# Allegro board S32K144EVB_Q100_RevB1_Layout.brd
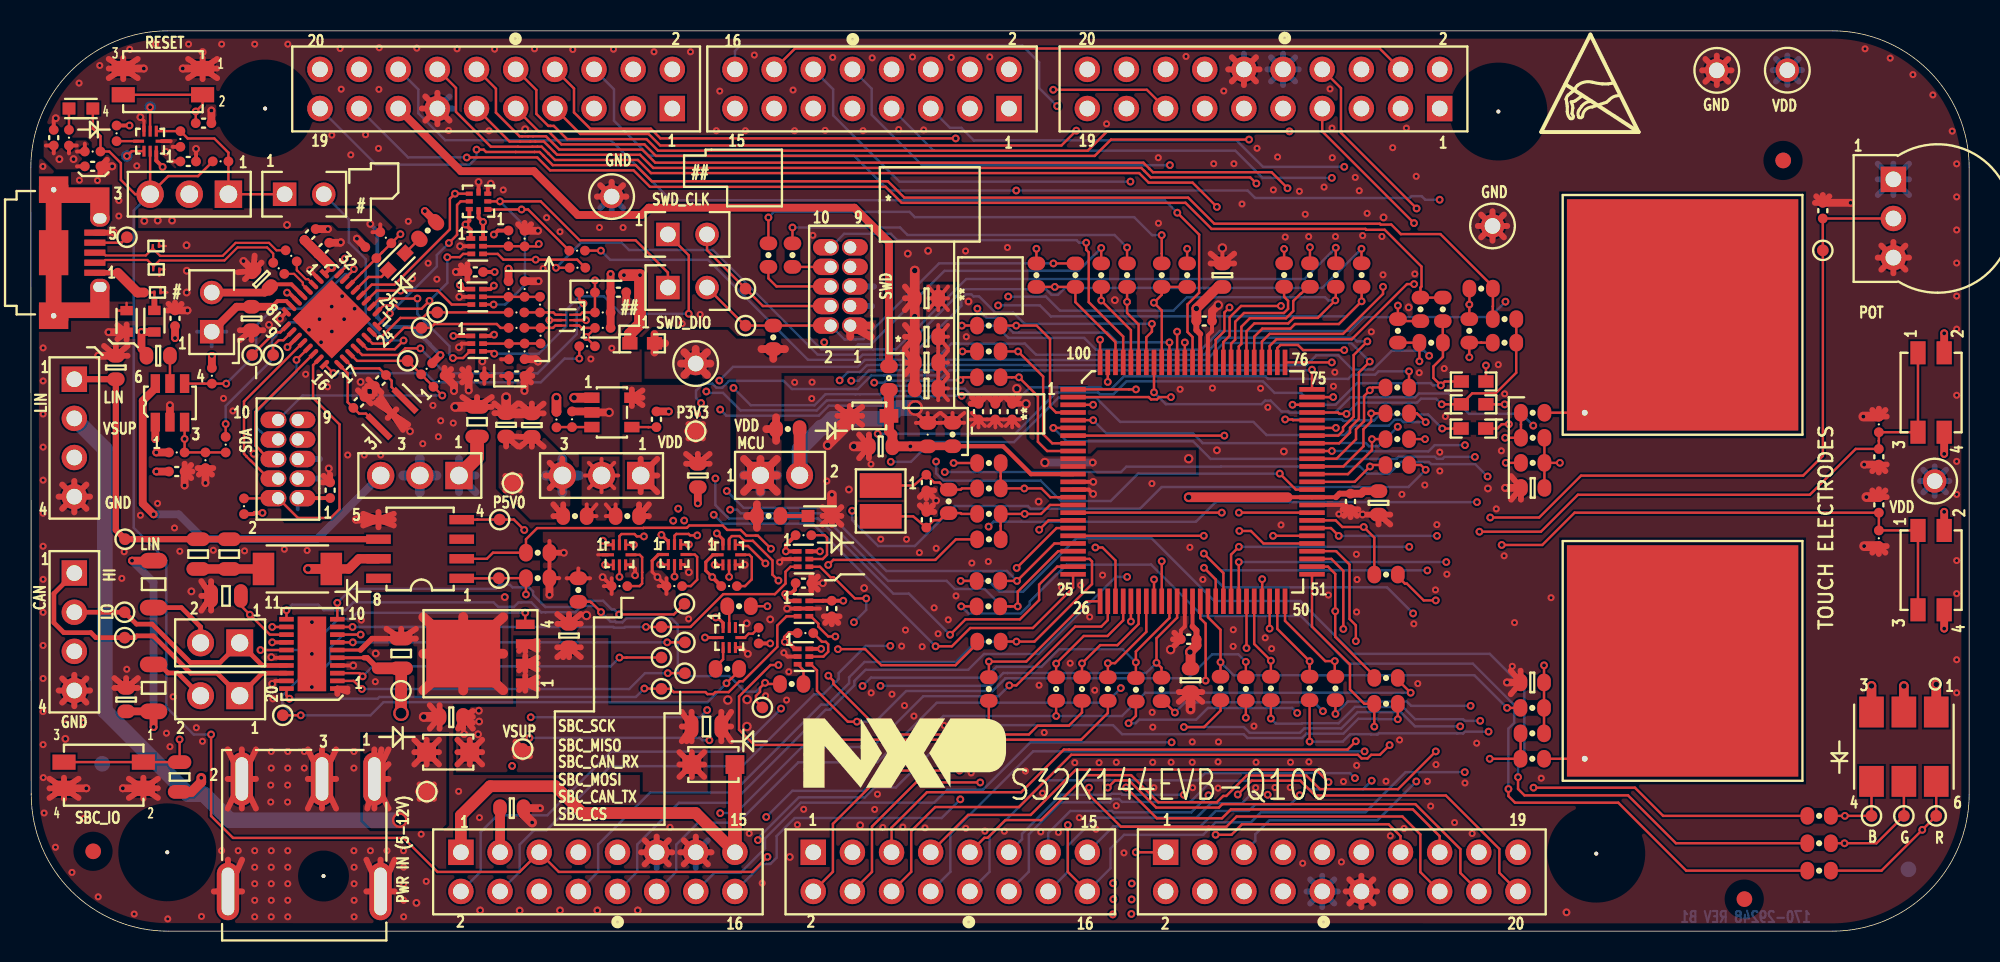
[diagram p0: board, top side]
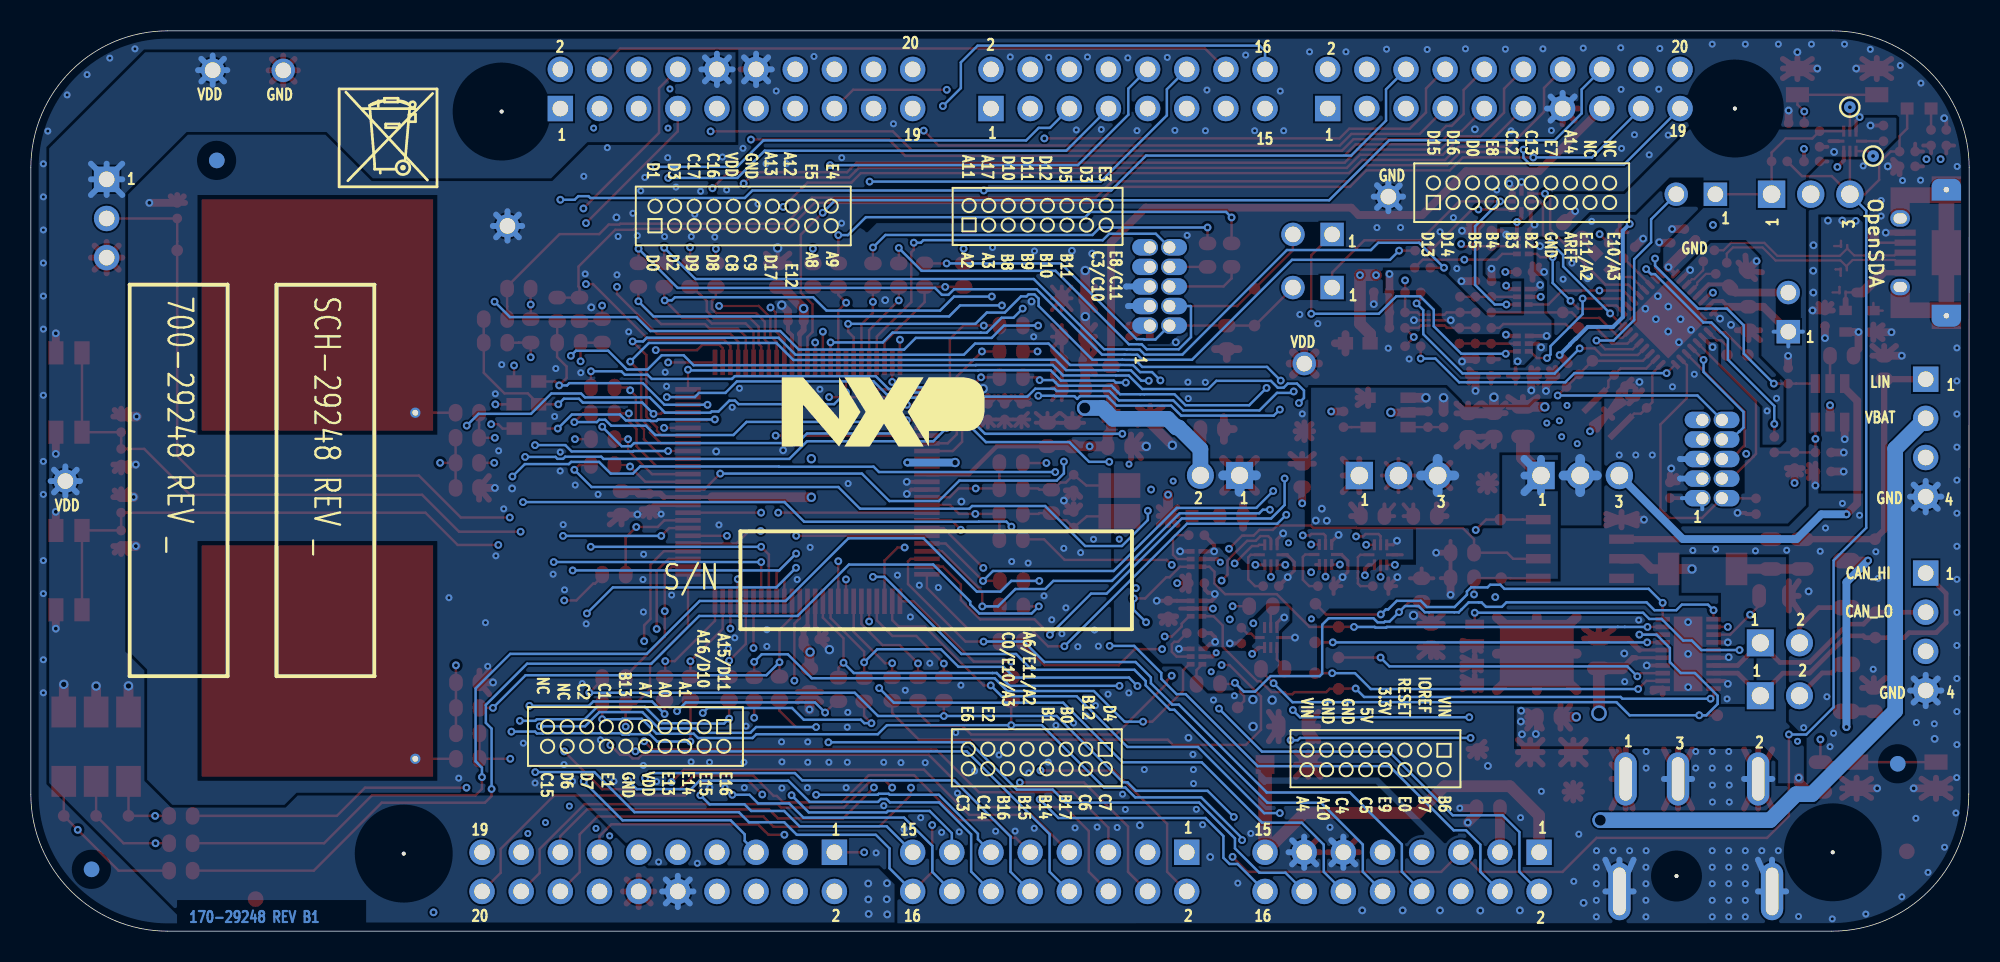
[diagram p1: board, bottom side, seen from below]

Outline 125.76 x 58.42 mm; copper layers: TOP, L2_GND, L3_MIX, BOTTOM. Coordinates in mm from the lower left corner of the outline.
Outline path: 0,49.53 0.03,8.89 0.03,8.89 arc(2.63,2.6) 8.92,0 116.87,0 arc(123.15,2.6) 125.76,8.89 125.76,49.53 arc(123.15,55.82) 116.87,58.42 8.89,58.42 arc(2.6,55.82) 0,49.53

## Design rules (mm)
net group CLOCK: nets SDA_EXTAL SDA_XTAL
net group SDA_USB_CONN_D: nets SDA_USB_CONN_DN SDA_USB_CONN_DP
net group USB_SI_CONN_D: nets SDA_USB_DN SDA_USB_DP
net group POW: nets MIC2005_CSLEW P5V_SDA POWER_EN SDA_RST SDA_USB_P5V_SENSE VREFH VTRG_EN
net group POWER_SPACE: nets P5V0_SDA_USB_CONN_VBUS P5V_SDA_PSW PWR_LED SDA_VOUT33 VIN
nets with their own width: min track width 0.254; nets GND

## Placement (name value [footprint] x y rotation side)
C1  1000pF  [CC0402_25]  11.21 52.43 0 top
C2  4.7uF  [CC0402_25]  1.49 51.49 90 top
C3  4.7uF  [CC0402_25]  10.21 49.94 0 top
C4  0.1UF  [CC0402_25]  4.01 49.63 0 top
C5  0.1UF  [CC0402_25]  116.26 46.75 90 top
C6  1.0UF  [CC0402_25]  18.12 45.2 45 top
C7  0.1UF  [CC0402_25]  19 44.31 45 top
C8  4.7uF  [CC0402_25]  28.83 42.77 180 top
C9  2.2UF  [CC0603_OV]  14.97 42.31 135 top
C10  0.1UF  [CC0402_25]  38.12 41.46 0 top
C11  10uF  [CC0402_25]  9.35 39.77 90 top
C12  10uF  [CC0603_OV]  14.32 39.75 270 top
C15  18PF  [CC0603_OV]  8.26 37.34 0 top
C16  0.1UF  [CC0402_25]  119.89 30.78 270 top
C17  220PF  [CC0603_OV]  5.51 36.58 90 top
C18  4.7uF  [CC0402_25]  28.92 36.03 180 top
C19  0.1UF  [CC0402_25]  31.52 36.03 0 top
C20  22PF  [CC0402_25]  22.68 35.73 225 top
C21  10uF  [CC0603_OV]  30.84 32.85 90 top
C22  0.1uF  [CC0603_OV]  32.5 32.84 90 top
C23  22PF  [CC0402_25]  21.29 34.31 45 top
C24  10uF  [CC0603_OV]  43.27 29.57 270 top
C25  0.1UF  [CC0402_25]  9.47 29.82 0 top
C26  0.1UF  [CC0402_25]  19.42 28.61 90 top
C27  6.8uF  [CC0805_OV]  28.95 33.06 90 top
C28  0.1UF  [CC0402_25]  119.9 27.66 90 top
C29  0.01uf  [CC0603_OV]  27.28 13.9 180 top
C40  4700 PF  [CC0603_OV]  6.18 15.02 90 top
C43  1UF  [CC0603_OV]  58.11 38.57 180 top
C47  0.1uF  [CC0603_OV]  34.92 19.18 90 top
C49  2.2UF  [CC0603_OV]  31.2 7.98 0 top
C59  0.01UF  [CC0402_25]  40.59 33.21 90 top
C126  12PF  [CC0402_25]  58.1 29.11 270 top
C127  12PF  [CC0402_25]  58.1 26.69 90 top
C128  22uF  [CC0805_OV]  43.83 13.28 0 top
C129  1UF  [CC0603_OV]  58.11 35.22 180 top
C131  1UF  [CC0603_OV]  58.11 36.89 180 top
C133  1UF  [CC0603_OV]  77.3 42.56 90 top
C137  1UF  [CC0603_OV]  75.24 16.28 270 top
C140  0.1uF  [CC0402_25]  62.58 33.71 90 top
C141  0.1uF  [CC0402_25]  75.12 18.94 180 top
C142  0.1uF  [CC0402_25]  76.13 39.59 0 top
C143  0.1uF  [CC0402_25]  85.62 27.88 270 top
C144  0.1uF  [CC0402_25]  61.48 33.71 90 top
C145  0.1uF  [CC0402_25]  63.67 33.71 90 top
C146  1UF  [CC0603_OV]  87.43 27.79 270 top
C147  1000PF  [CC0603_OV]  58.11 41.06 180 top
C148  1000PF  [CC0603_OV]  55.14 31.46 180 top
C533  10pF  [CC0603_OV]  97.44 28.76 180 top
C535  10pF  [CC0603_OV]  97.41 16.14 180 top
C536  6.8uF  [CC0805_OV]  12.66 21.76 180 top
C537  0.1UF  [CC0402_25]  51.96 20.93 270 top
C538  0.1UF  [CC0402_25]  50.13 22.58 0 top
D1  RED  [LED_0603]  3.25 53.38 0 top
D2  LED GREEN  [LED_0603]  23.73 43.44 225 top
D3  GREEN  [LED_0603]  51.2 26.94 0 top
D6  PMEG3050EP  [SOD-128]  17.29 23.5 180 top
D7  BZX384-C30  [SOD323]  54.4 33.44 90 top
D9  PNS40010ER  [SOD123W]  27.08 11.62 180 top
D11  LED RED/GRN/BL  [LED6_5X6MM]  121.52 11.97 270 top
D13  PNS40010ER  [SOD123W]  44.28 10.81 0 top
D17  PESD5V0R1BSF  [DSN0603-2]  8.22 41.45 180 top
D18  PESD5V0R1BSF  [DSN0603-2]  8.12 44.46 180 top
D19  PESD5V0R1BSF  [DSN0603-2]  8.14 42.94 180 top
J1  CON 2X8  [CON2X8_2P54_TH]  63.46 53.38 270 top
J2  CON 2X10  [CON20_2P54_TH]  41.62 53.38 270 top
J3  CON 2X8  [CON2X8_2P54_TH]  27.9 5.12 90 top
J4  CON 2X8  [CON2X8_2P54_TH]  50.76 5.12 90 top
J5  CON 2X10  [CON20_2P54_TH]  73.62 5.12 90 top
J6  CON 2X10  [CON20_2P54_TH]  91.4 53.38 270 top
J7  USB_MICRO_AB  [CON_MICROAB_10F_25_SM_RA]  1.58 44.02 0 top
J8  HDR 1X2 TH  [SH_HDR102_BOTTOM]  41.33 45.21 90 top
J9  HDR 1X2 TH  [SH_HDR102_BOTTOM]  11.73 38.9 180 top
J10  HDR 1X3  [HDR103_A]  39.57 29.57 270 top
J11  HDR 1X4 RA  [CON_HDR_4M_100_TH_RA]  2.82 35.81 270 top
J12  HDR 2X5  [CON_2RH_10_50]  17.32 28.09 90 top
J13  HDR 1X4 RA  [CON_HDR_4M_100_TH_RA]  2.82 23.24 270 top
J14  HDR 2X5  [CON_2RH_10_50]  53.16 39.29 90 top
J15  HDR1X2  [HDR1X2_5P48X2P69]  47.34 29.58 0 top
J16  CON PWR 3  [CON3_PWR_JACK_TH_PJ051A]  22.29 9.88 90 top
J104  HDR 1X3  [HDR103_A]  12.82 47.82 270 top
J105  HDR 1X2 TH  [SH_HDR102_BOTTOM]  16.46 47.82 90 top
J106  HDR 1X2 TH  [SH_HDR102_BOTTOM]  41.33 41.76 90 top
J107  HDR 1X3  [HDR103_A]  27.78 29.57 270 top
J108  HDR1X2  [HDR1X2_5P48X2P69]  13.55 18.71 180 top
J109  HDR1X2  [HDR1X2_5P48X2P69]  13.55 15.28 180 top
L1  330 OHM  [IND_1608]  8.02 39.58 270 top
L2  330 OHM  [IND_1608]  6.21 39.57 270 top
NOREF  -  []  45.68 2.58 90 top
NOREF#2  -  []  3.1 56.28 0 top
NOREF#3  -  []  8.02 41.45 0 top
NOREF#4  -  []  45.87 22.75 90 top
NOREF#5  -  []  121.52 9.72 0 top
NOREF#6  -  []  44.06 52.07 90 top
NOREF#7  -  []  25.68 10.67 90 top
NOREF#8  -  []  45.51 18.43 90 top
NOREF#9  -  []  123.57 14.52 90 top
NOREF#10  -  []  37.46 23.8 0 top
NOREF#11  -  []  25.68 12.57 0 top
NOREF#12  -  []  180.28 58.67 0 top
NOREF#13  -  []  70.16 6.42 90 top
NOREF#14  -  []  11.01 18.71 0 top
NOREF#15  -  []  116.87 0 90 top
NOREF#16  -  []  45.7 23.77 90 top
NOREF#17  -  []  53.34 39.01 0 top
NOREF#18  -  [unnamed#2]  8.85 5.12 0 top
NOREF#19  -  []  68.54 2.58 90 top
NOREF#20  -  []  45.5 23.8 90 top
NOREF#21  -  []  8.89 58.42 0 top
NOREF#22  -  []  98.1 6.42 90 top
NOREF#23  -  [unnamed#2]  113.69 50.01 0 top
NOREF#24  -  [unnamed#2]  111.17 2.08 0 top
NOREF#25  -  []  78.85 41.27 0 top
NOREF#26  -  []  95.76 36.47 270 top
NOREF#27  -  []  2.33 11.92 0 top
NOREF#28  -  []  42.16 23.79 90 top
NOREF#29  -  []  122.43 26 0 top
NOREF#30  -  []  15.02 11.14 0 top
NOREF#31  -  []  125.76 8.89 90 top
NOREF#32  -  []  45.68 13.66 0 top
NOREF#33  -  []  7.8 44.62 0 top
NOREF#34  -  []  11.99 52.07 0 top
NOREF#35  -  [unnamed#2]  4.05 5.18 0 top
NOREF#36  -  []  44.59 18.43 0 top
NOREF#37  -  []  7.9 41.61 0 top
NOREF#38  -  []  38.39 23.8 90 top
NOREF#39  -  []  34.42 40 0 top
NOREF#40  -  []  37.79 23.77 0 top
NOREF#41  -  []  118.47 14.52 0 top
NOREF#42  -  []  7.94 42.94 0 top
NOREF#43  -  []  15.02 14.57 90 top
NOREF#44  -  []  7.82 43.1 0 top
NOREF#45  -  []  51.49 7.8 0 top
NOREF#46  -  []  35.9 38.07 90 top
NOREF#47  -  []  19.88 15.74 90 top
NOREF#48  -  []  47.3 6.42 0 top
NOREF#49  -  []  10.97 53.32 90 top
NOREF#50  -  []  7.01 51.88 0 top
NOREF#51  -  []  7.13 8.32 90 top
NOREF#52  -  []  45.68 11.76 90 top
NOREF#53  -  []  7.3 9.27 90 top
NOREF#54  -  []  92.95 6.42 0 top
NOREF#55  -  []  45.68 53.38 90 top
NOREF#56  -  []  6.99 51.26 90 top
NOREF#57  -  []  47.3 6.42 90 top
NOREF#58  -  []  8.85 5.12 0 top
NOREF#59  -  []  45.71 18.4 90 top
NOREF#60  -  []  19.29 27.55 0 top
NOREF#61  -  []  20.03 15.44 90 top
NOREF#62  -  []  70.16 6.42 0 top
NOREF#63  -  []  122.43 20.85 90 top
NOREF#64  -  []  34.85 38.07 0 top
NOREF#65  -  []  7.94 50.64 90 top
NOREF#66  -  []  8.85 5.12 0 top
NOREF#67  -  []  0.03 8.89 0 top
NOREF#68  -  []  5.99 55.97 0 top
NOREF#69  -  []  121.48 37.35 0 top
NOREF#70  -  []  45.87 22.75 0 top
NOREF#71  -  []  0 49.53 0 top
NOREF#72  -  []  -35.57 -162.37 0 top
NOREF#73  -  []  38.59 23.77 90 top
NOREF#74  -  []  6.17 56.92 0 top
NOREF#75  -  []  27.9 5.12 0 top
NOREF#76  -  []  98.01 51.85 0 top
NOREF#77  -  []  7.82 42.78 90 top
NOREF#78  -  []  17.14 52.07 90 top
NOREF#79  -  []  34.42 39.65 90 top
NOREF#80  -  []  47.34 29.58 0 top
NOREF#81  -  []  61.77 52.07 0 top
NOREF#82  -  []  16.58 20.24 0 top
NOREF#83  -  []  44.06 52.07 0 top
NOREF#84  -  []  11.15 54.27 90 top
NOREF#85  -  []  50.13 9.31 0 top
NOREF#86  -  []  2.15 10.97 0 top
NOREF#87  -  []  41.36 23.79 0 top
NOREF#88  -  []  41.96 23.82 90 top
NOREF#89  -  []  15.02 14.57 0 top
NOREF#90  -  []  13.93 22.9 0 top
NOREF#91  -  []  -381.97 187.81 0 top
NOREF#92  -  []  7.8 44.29 90 top
NOREF#93  -  []  50.76 5.12 0 top
NOREF#94  -  []  116.87 0 0 top
NOREF#95  -  []  122.43 32.38 90 top
NOREF#96  -  []  -16.59 -34.16 0 top
NOREF#97  -  []  11.01 15.28 0 top
NOREF#98  -  []  15.02 11.14 90 top
NOREF#99  -  []  7.9 41.28 90 top
NOREF#100  -  [unnamed#2]  95.21 53.18 0 top
NOREF#101  -  []  121.48 21.03 90 top
NOREF#102  -  []  -408 -337.34 0 top
NOREF#103  -  []  122.43 37.53 0 top
NOREF#104  -  []  44.91 18.4 0 top
NOREF#105  -  []  19.29 24.85 90 top
NOREF#106  -  []  121.48 32.55 90 top
NOREF#107  -  []  45.68 53.38 0 top
NOREF#108  -  []  7.92 44.46 0 top
NOREF#109  -  []  19.88 15.74 90 top
NOREF#110  -  []  121.48 25.83 0 top
NOREF#111  -  []  7.74 51.91 0 top
NOREF#112  -  []  -67.9 -131.95 0 top
NOREF#113  -  []  119.42 9.72 90 top
NOREF#114  -  []  8.85 5.12 0 top
NOREF#115  -  []  44.9 23.77 0 top
NOREF#116  -  []  16.43 21.04 0 top
NOREF#117  -  [unnamed#2]  101.56 5.03 0 top
NOREF#118  -  []  44.58 23.8 0 top
NOREF#119  -  []  66.92 52.07 90 top
NOREF#120  -  []  15.09 23.5 0 top
NOREF#121  -  [unnamed#2]  15.2 53.38 0 top
NOREF#122  -  []  41.03 23.81 0 top
NOREF#123  -  []  91.82 42.06 180 bottom
NOREF#124  -  []  79.72 19.6 180 bottom
NOREF#125  -  [unnamed#2]  113.69 50.01 180 bottom
NOREF#126  -  []  54.61 8.05 180 bottom
NOREF#127  -  []  54.66 15.42 180 bottom
NOREF#128  -  [unnamed#2]  4.63 10.86 180 bottom
NOREF#129  -  []  29.4 21.3 180 bottom
NOREF#130  -  []  105.75 48.3 180 bottom
NOREF#131  -  []  77.03 31.45 180 bottom
NOREF#132  -  []  109.82 41.95 270 bottom
NOREF#133  -  []  119.34 41.95 270 bottom
NOREF#134  -  [unnamed#2]  121.81 4.01 180 bottom
Q1  PHPT61003PY  [LFPAK5_1P27_5X4]  29.1 18 90 top
R1  4.7K  [RC0402_25]  5.57 51.77 90 top
R2  330 OHM  [RC0402_25]  2.47 51.49 270 top
R3  10.0K  [RC0402_25]  9.7 51.4 90 top
R4  180K  [RC0402_25]  4.01 50.59 0 top
R5  0  [RC0402_25]  12.31 49.95 180 top
R12  220  [RC0603_OV]  25.75 45.46 225 top
R13  5K  [POT3_3352T]  120.84 48.78 270 top
R14  4.7K  [RC0402_25]  23.03 45 315 top
R15  4.7K  [RC0402_25]  30.99 44.95 270 top
R16  10.0K  [RC0402_25]  32.03 44.94 90 top
R18  0  [RC0402_25]  35.44 44.16 0 top
R20  10.0K  [RC0402_25]  22.06 44.03 135 top
R21  33  [RC0402_25]  16.89 43.82 315 top
R24  0  [RC0402_25]  35.47 43.05 180 top
R25  33  [RC0402_25]  16.09 43.01 315 top
R30  4.7K  [RC0402_25]  30.99 41.67 270 top
R31  10.0K  [RC0402_25]  32.03 41.67 90 top
R32  0  [RC0402_25]  36.09 41.45 180 top
R35  0  [RC0402_25]  33.04 40.65 90 top
R38  0  [RC0402_25]  31.51 40.15 180 top
R39  10.0K  [RC0402_25]  37.11 40.15 0 top
R41  0  [RC0402_25]  31.51 39.15 180 top
R42  10.0K  [RC0402_25]  37.11 39.15 180 top
R44  10.0K  [RC0402_25]  119.9 32.88 90 top
R47  0  [RC0402_25]  33.07 38.64 270 top
R49  0  [RC0402_25]  36.09 37.95 180 top
R51  10.0K  [RC0402_25]  32.03 37.62 270 top
R52  4.7K  [RC0402_25]  31.02 37.61 90 top
R56  330  [RC0603_OV]  47.87 26.94 180 top
R57  4.7K  [RC0402_25]  25.68 36.49 225 top
R60  10.0K  [RC0402_25]  11.75 36.04 270 top
R62  10.0K  [RC0402_25]  26.48 35.68 45 top
R63  0  [RC0603_OV]  38.7 26.93 180 top
R64  0  [RC0603_OV]  35.3 26.93 0 top
R68  15K  [RC0402_25]  11.33 30.56 270 top
R69  1.0K  [RC0402_25]  12.64 31.57 270 top
R70  10.0K  [RC0402_25]  9.47 31.06 0 top
R74  10.0K  [RC0402_25]  119.9 25.49 270 top
R77  10.0K  [RC0402_25]  13.83 27.57 90 top
R80  2K  [RC0805_OV]  10.86 24.47 270 top
R81  0  [RC0603_OV]  62.16 25.42 0 top
R84  0  [RC0603_OV]  62.16 27.08 180 top
R88  0  [RC0603_OV]  62.16 28.73 180 top
R90  0  [RC0603_OV]  62.16 30.38 0 top
R91  1.0M  [RC0603_OV]  59.55 27.89 270 top
R92  60.4  [RC1206_OV]  7.96 15.79 90 top
R95  220  [RC0603_OV]  116.02 7.48 180 top
R96  220  [RC0603_OV]  116.02 5.7 180 top
R97  220  [RC0603_OV]  116.02 3.93 180 top
R98  60.4  [RC1206_OV]  7.96 22.52 270 top
R99  1K  [RC0603_OV]  59.8 32.23 270 top
R103  0  [RC0603_OV]  58.18 32.22 270 top
R109  0  [RC0603_OV]  55.67 35.89 90 top
R117  0  [RC0603_OV]  49.11 32.58 0 top
R119  0  [RC0603_OV]  47.85 43.87 90 top
R120  0  [RC0603_OV]  49.41 43.87 90 top
R121  10K  [RC0603_OV]  48.17 38.53 90 top
R122  0  [RC0603_OV]  67.77 42.57 90 top
R123  0  [RC0603_OV]  73.37 42.56 90 top
R124  0  [RC0603_OV]  88.65 35.28 0 top
R125  0  [RC0603_OV]  88.65 33.6 0 top
R126  0  [RC0603_OV]  88.65 31.93 0 top
R127  0  [RC0603_OV]  69.45 42.56 90 top
R128  0  [RC0603_OV]  71.12 42.57 90 top
R129  0  [RC0603_OV]  88.65 30.25 180 top
R130  0  [RC0603_OV]  69.87 15.71 90 top
R131  0  [RC0603_OV]  68.2 15.71 90 top
R132  0  [RC0603_OV]  66.52 15.71 90 top
R133  0  [RC0603_OV]  87.92 16.43 180 top
R134  0  [RC0603_OV]  87.92 14.76 180 top
R135  0  [RC0603_OV]  62.15 15.71 90 top
R136  0  [RC0603_OV]  62.15 37.62 0 top
R137  0  [RC0603_OV]  62.15 35.94 0 top
R146  0  [RC0603_OV]  77.18 15.75 90 top
R147  0  [RC0603_OV]  87.92 23.14 180 top
R152  0  [RC0603_OV]  84.64 15.75 270 top
R153  0  [RC0603_OV]  82.96 15.75 270 top
R154  0  [RC0603_OV]  62.12 21.08 180 top
R155  0  [RC0603_OV]  62.12 22.73 180 top
R156  0  [RC0603_OV]  62.15 39.29 180 top
R161  0  [RC0603_OV]  84.66 42.57 90 top
R162  0  [RC0603_OV]  86.34 42.57 90 top
R164  0  [RC0603_OV]  80.45 15.75 270 top
R165  0  [RC0603_OV]  82.99 42.57 90 top
R166  0  [RC0603_OV]  73.36 15.69 270 top
R167  0  [RC0603_OV]  81.31 42.57 90 top
R168  0  [RC0603_OV]  71.69 15.67 270 top
R169  0  [RC0402_25]  34.1 33.2 270 top
R170  0  [RC0402_25]  35.11 33.22 270 top
R171  2K  [RC0805_OV]  12.87 24.47 270 top
R172  0  [RC0603_OV]  97.44 33.64 180 top
R525  4.7K  [RC0603_OV]  97.44 32.01 180 top
R527  0  [RC0603_OV]  97.41 11.19 180 top
R528  4.7K  [RC0603_OV]  97.41 12.84 180 top
R529  0  [RC0603_OV]  62.16 18.79 0 top
R530  4.7K  [RC0603_OV]  32.89 24.56 180 top
R532  0  [RC0603_OV]  78.83 15.72 270 top
R533  0  [RC0603_OV]  97.44 30.39 0 top
R534  0  [RC0603_OV]  97.41 14.49 0 top
R535  2.2  [RC0805_OV]  24.03 18.02 90 top
R536  4.7K  [RC0603_OV]  35.52 22.14 270 top
R537  10k  [RC0805_OV]  9.65 10 90 top
R538  4.7K  [RC0603_OV]  32.89 22.91 180 top
R539  0  [RC0603_OV]  95.61 39.72 0 top
R540  0  [RC0603_OV]  91.61 40.35 270 top
R541  0  [RC0603_OV]  95.61 38.18 180 top
R542  0  [RC0603_OV]  90.85 38.18 180 top
R543  0  [RC0603_OV]  93.32 38.95 270 top
R544  0  [RC0603_OV]  88.69 38.95 270 top
R545  0  [RC0603_OV]  75.02 42.56 270 top
R546  0  [RC0603_OV]  65.24 42.57 270 top
R556  4.7K  [RC0402_25]  38.19 22.39 180 top
R558  4.7K  [RC0402_25]  45.3 22.39 180 top
R559  4.7K  [RC0402_25]  50.13 25.69 0 top
R560  4.7K  [RC0402_25]  41.74 22.39 180 top
R562  4.7K  [RC0402_25]  47.22 19.18 270 top
R563  0  [RC0603_OV]  45.95 21.08 0 top
R564  4.7K  [RC0402_25]  50.25 19.34 0 top
R565  0  [RC0603_OV]  45.19 17.02 180 top
R566  0  [RC0603_OV]  49.36 16.04 0 top
R567  0  [RC0603_OV]  94.09 41.69 180 top
R568  0  [RC0603_OV]  90.16 40.35 270 top
SH1  0  [SH0603]  39.66 38.15 0 top
SH11  0  [SH0603]  93.6 35.67 0 top
SH12  0  [SH0603]  93.6 34.19 0 top
SH13  0  [SH0603]  93.59 32.61 180 top
SW2  EVQ-P2402W  [SW4_SPST_4P8X3P6_2P5]  123.28 34.95 90 top
SW3  EVQ-P2402W  [SW4_SPST_4P8X3P6_2P5]  123.28 23.43 90 top
SW5  EVQ-P2402W  [SW4_SPST_4P8X3P6_2P5]  8.57 55.12 0 top
SW7  Electrode  [ELECTRODE_SQ_15MM]  107.16 39.99 90 top
SW8  Electrode  [ELECTRODE_SQ_15MM]  107.16 17.54 90 top
SW9  EVQ-P2402W  [SW4_SPST_4P8X3P6_2P5]  4.73 10.12 0 top
TP1  TEST POINT BLACK  [TEST_LOOP]  109.38 55.85 270 top
TP4  TEST POINT BLACK  [TEST_LOOP]  113.96 55.87 270 top
TP5  -  [TPAD_030]  116.26 44.18 270 top
TP6  -  [TPAD_030]  6.24 45.03 90 top
TP7  -  [TPAD_030]  26.37 40.15 315 top
TP8  -  [TPAD_030]  25.35 39.15 315 top
TP9  TEST POINT BLACK  [TEST_LOOP]  43.13 36.83 270 top
TP10  -  [TPAD_030]  14.36 37.39 90 top
TP11  -  [TPAD_030]  15.72 37.39 90 top
TP12  -  [TPAD_030]  24.44 37.01 90 top
TP13  -  [TPAD_030]  43.13 32.44 90 top
TP14  -  [TPAD_030]  31.25 29.07 225 top
TP15  -  [TPAD_030]  24.02 15.6 270 top
TP16  TEST POINT BLACK  [TEST_LOOP]  123.52 29.2 270 top
TP17  TEST POINT BLACK  [TEST_LOOP]  94.83 45.76 270 top
TP18  -  [TPAD_030]  6.11 25.43 90 top
TP19  -  [TPAD_030]  6.09 19.04 180 top
TP20  -  [TPAD_030]  42.44 18.74 90 top
TP21  -  [TPAD_030]  42.44 16.74 90 top
TP22  -  [TPAD_030]  6.08 20.7 180 top
TP23  -  [TPAD_030]  40.91 19.74 0 top
TP24  -  [TPAD_030]  16.34 14.01 0 top
TP25  -  [TPAD_030]  40.91 17.76 0 top
TP27  -  [TPAD_030]  42.41 21.24 180 top
TP28  -  [TPAD_030]  119.42 7.48 270 top
TP29  -  [TPAD_030]  121.52 7.48 0 top
TP30  -  [TPAD_030]  123.62 7.48 90 top
TP31  -  [TPAD_030]  46.37 41.69 180 top
TP32  TEST POINT BLACK  [TEST_LOOP]  37.68 47.66 270 top
TP33  -  [TPAD_030]  40.91 15.72 180 top
TP34  -  [TPAD_030]  46.37 39.29 180 top
TP35  -  [TPAD_030]  30.37 22.91 0 top
TP36  -  [TPAD_030]  31.91 11.82 0 top
TP37  -  [TPAD_030]  30.41 26.71 0 top
TP38  -  [TPAD_030]  25.69 9.05 0 top
TP500  -  [TPAD_030]  7.74 53.47 90 bottom
TP501  -  [TPAD_030]  6.23 50.29 90 bottom
TP502  -  [TPAD_030]  47.46 14.52 0 top
U1  NTSX2102GU8H  [XQFN8_1P45X1P25MM]  7.74 51.26 180 top
U2  74LVC2T45GM,125  [QFN8_1P6X1P6MM]  29.05 47.35 180 top
U4  74LVCH1T45  [UDFN6_1X1P5MM]  28.96 44.44 0 top
U7  74LVCH1T45  [UDFN6_1X1P5MM]  28.96 41.16 0 top
U8  MK20DX128VFM5  [QFN32_S142EP]  19.52 39.71 315 top
U9  74LVC2G14GF,132  [SOT891_6P_0P35_1P05X1P05]  34.83 39.65 180 top
U10  74LVCH1T45  [UDFN6_1X1P5MM]  28.96 38.12 0 top
U11  MIC2005-0.8YM6  [SOT23-6_A]  9.03 34.28 90 top
U15  SPX3819M5-L-3-3  [SOT23_5S]  37.7 33.66 270 top
U17  PS32K144HFT0VLLT  [LQFP100_0P5_14X14]  75.37 29.16 0 top
U19  UJA1169TK/F  [SON20_0P5_3P6X5P6]  18.23 17.99 90 top
U21  TJA1027T/20  [SO8_1P27_4X5]  25.26 24.8 180 top
U26  NTSX2102GU8H  [XQFN8_1P45X1P25MM]  38.19 24.42 0 top
U28  NTSX2102GU8H  [XQFN8_1P45X1P25MM]  45.3 24.42 0 top
U29  74LVCH1T45  [UDFN6_1X1P5MM]  50.13 24.15 0 top
U30  NTSX2102GU8H  [XQFN8_1P45X1P25MM]  41.76 24.44 0 top
U31  74LVCH1T45  [UDFN6_1X1P5MM]  50.13 20.93 0 top
U32  NTSX2102GU8H  [XQFN8_1P45X1P25MM]  45.31 19.05 0 top
U33  74LVCH1T45  [UDFN6_1X1P5MM]  50.13 17.82 0 top
Y1  8.00MHZ  [XTAL3_3P35X1P45_SM]  23.43 33.58 45 top
Y3  8MHZ  [XTAL2_3P3X2P6]  55.14 27.92 270 top

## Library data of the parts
C1 C6 C9 C11 C16 C17 C20-C24 C27-C29 C40 C43 C47 C49 C126-C129 C131 C133 C137 C140-C148 C536 = CAP_NP
C2-C5 C7 C8 C10 C12 C18 C19 C25 C26 C533 C535 C537 C538 = CAP_NP: tolerance: 10%
C15 = CAP_NP: tolerance: 5%
C59 = CAP_NP: tolerance: 20%
D1-D3 = LED
D6 = DIODE_SCHTKY
D7 = ZDIODE
D9 D13 = DIODE
D11 = LED_TRI_COLOR
D17-D19 = DIODE_BIDIR
J1 J3 J4 = HDR_2X8_M
J2 J5 J6 = CONN_HDR_10X2
J7 = MICRO_USB_CONN_10PIN
J8 J9 J15 J105 J106 J108 J109 = CONN_HDR_2X1
J10 J104 J107 = CONN_HDR_3X1
J11 J13 = CONN_HDR_4X1
J12 J14 = CONN_HDR_5X2: User Part Number: 210-07961-00
J16 = DC_POWER_JACK_SHD
L1 L2 = BEAD
Q1 = PMOS_5P
R1 R14 R15 R30 R44 R52 R57 R60 R68-R70 R74 R556 R558-R560 R562 R564 = RES: tolerance: 1%
R2 R4 R12 R20 R21 R25 R32 R35 R38 R41 R47 R49 R56 R62-R64 R77 R80 R81 R84 R88 R90-R92 R95-R99 R103 R109 R117 R119-R137 R146 R147 R152-R156 R161 R162 R164-R172 R525 R527-R530 R532-R546 R563 R565-R568 = RES
R3 R5 R16 R18 R24 R31 R39 R42 R51 = RES: tolerance: 5%
R13 = POT: tolerance: 20%
SH1 SH11-SH13 = RES_SHORT-2
SW2 SW3 SW5 SW9 = EDGE_MOUNT_PB_SW_2
SW7 SW8 = ELECTRODE
TP1 TP4-TP25 TP27-TP38 TP500-TP502 = TestLoop
U1 U26 U28 U30 U32 = NTSX2102GU8H_8P
U2 = 74LVC2T45GM_8P
U4 U7 U10 U29 U31 U33 = 74LVCH1T45_6P
U8 = PK20DX128V_QFN_32P
U9 = NC7WP14
U11 = MIC2005-0.8YM6
U15 = SPX3819M5_FIX_5P
U17 = PS32K144_LQFP_100P_A
U19 = UJA1169TKF
U21 = TJA1027T_8P
Y1 = XTAL_CS
Y3 = XTAL_CS10

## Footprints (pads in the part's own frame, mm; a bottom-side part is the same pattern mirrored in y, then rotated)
CC0402_25
  round 0.635 smd: 1(-0.508,0) 2(0.508,0)
CC0603_OV
  oval 0.889x1.143 smd: 1(-0.762,0) 2(0.762,0)
CC0805_OV
  oval 0.889x1.524 smd: 1(-0.965,0) 2(0.965,0)
CON2X8_2P54_TH
  rect 1.651x1.651 hole 1.016: 1(0,0)
  round 1.651 hole 1.016: 2(-2.54,0) 3(0,-2.54) 4(-2.54,-2.54) 5(0,-5.08) 6(-2.54,-5.08) 7(0,-7.62) 8(-2.54,-7.62) 9(0,-10.16) 10(-2.54,-10.16) 11(0,-12.7) 12(-2.54,-12.7) 13(0,-15.24) 14(-2.54,-15.24) 15(0,-17.78) 16(-2.54,-17.78)
CON3_PWR_JACK_TH_PJ051A
  round 0.254 hole 2.54 unplated: (-6.3,3.3)
  oval 3.454x1.448 hole 2.819x0.813: 1(0,0) 2(0,8.6) 3(0,3.4)
  oval 3.734x1.448 hole 3.099x0.813: SH1(-7.3,9.5) SH2(-7.3,-0.4)
CON20_2P54_TH
  rect 1.651x1.651 hole 1.016: 1(0,0)
  round 1.651 hole 1.016: 2(-2.54,0) 3(0,-2.54) 4(-2.54,-2.54) 5(0,-5.08) 6(-2.54,-5.08) 7(0,-7.62) 8(-2.54,-7.62) 9(0,-10.16) 10(-2.54,-10.16) 11(0,-12.7) 12(-2.54,-12.7) 13(0,-15.24) 14(-2.54,-15.24) 15(0,-17.78) 16(-2.54,-17.78) 17(0,-20.32) 18(-2.54,-20.32) 19(0,-22.86) 20(-2.54,-22.86)
CON_2RH_10_50
  oval 1.067x1.676 hole 0.787: 1(0,0) 2(0,1.27) 3(1.27,0) 4(1.27,1.27) 5(2.54,0) 6(2.54,1.27) 7(3.81,0) 8(3.81,1.27) 9(5.08,0) 10(5.08,1.27)
CON_HDR_4M_100_TH_RA
  rect 1.651x1.651 hole 1.016: 1(0,0)
  round 1.651 hole 1.016: 2(2.54,0) 3(5.08,0) 4(7.62,0)
CON_MICROAB_10F_25_SM_RA
  rect 1.372x0.406 smd: 1(2.575,-1.3) 2(2.575,-0.65) 3(2.575,0) 4(2.575,0.65) 5(2.575,1.3)
  oval 1.27x1.067 hole 0.864x0.66: 6(2.9,2.225) 7(2.9,-2.225)
  rect 1.905x2.921 smd: 8(-0.1,0)
  custom 0.356x0.356 hole 1.524x0.838: 9(-0.1,4.09) 10(-0.1,-4.09)
DSN0603-2
  rect 0.152x0.254 smd: 1(-0.2,0) 2(0.2,0)
ELECTRODE_SQ_15MM
  rect 15.011x15.011 hole 0.381: 1(-6.35,6.349)
HDR1X2_5P48X2P69
  rect 1.753x1.753 hole 1.118: 1(0,0)
  round 1.753 hole 1.118: 2(2.54,0)
HDR103_A
  rect 1.778x1.778 hole 1.143: 1(0,0)
  round 1.778 hole 1.143: 2(0,-2.54) 3(0,-5.08)
IND_1608
  rect 0.61x0.813 smd: 1(-0.7,0) 2(0.7,0)
LED6_5X6MM
  rect 2.007x1.6 smd: A1(-2.25,2.1) A2(-2.25,0) A3(-2.25,-2.1) C1(2.25,2.1) C2(2.25,0) C3(2.25,-2.1)
LED_0603
  rect 0.838x0.787 smd: A(-0.775,0) C(0.775,0)
LFPAK5_1P27_5X4
  rect 0.61x1.219 smd: 1(-1.905,-2.975) 2(-0.635,-2.975) 3(0.635,-2.975) 4(1.905,-2.975)
  rect 4.394x4.801 smd: 5(0,1.05)
LQFP100_0P5_14X14
  rect 1.651x0.305 smd: 1(-7.75,6) 2(-7.75,5.5) 3(-7.75,5) 4(-7.75,4.5) 5(-7.75,4) 6(-7.75,3.5) 7(-7.75,3) 8(-7.75,2.5) 9(-7.75,2) 10(-7.75,1.5) 11(-7.75,1) 12(-7.75,0.5) 13(-7.75,0) 14(-7.75,-0.5) 15(-7.75,-1) 16(-7.75,-1.5) 17(-7.75,-2) 18(-7.75,-2.5) 19(-7.75,-3) 20(-7.75,-3.5) 21(-7.75,-4) 22(-7.75,-4.5) 23(-7.75,-5) 24(-7.75,-5.5) 25(-7.75,-6) 51(7.75,-6) 52(7.75,-5.5) 53(7.75,-5) 54(7.75,-4.5) 55(7.75,-4) 56(7.75,-3.5) 57(7.75,-3) 58(7.75,-2.5) 59(7.75,-2) 60(7.75,-1.5) 61(7.75,-1) 62(7.75,-0.5) 63(7.75,0) 64(7.75,0.5) 65(7.75,1) 66(7.75,1.5) 67(7.75,2) 68(7.75,2.5) 69(7.75,3) 70(7.75,3.5) 71(7.75,4) 72(7.75,4.5) 73(7.75,5) 74(7.75,5.5) 75(7.75,6)
  rect 0.305x1.651 smd: 26(-6,-7.75) 27(-5.5,-7.75) 28(-5,-7.75) 29(-4.5,-7.75) 30(-4,-7.75) 31(-3.5,-7.75) 32(-3,-7.75) 33(-2.5,-7.75) 34(-2,-7.75) 35(-1.5,-7.75) 36(-1,-7.75) 37(-0.5,-7.75) 38(0,-7.75) 39(0.5,-7.75) 40(1,-7.75) 41(1.5,-7.75) 42(2,-7.75) 43(2.5,-7.75) 44(3,-7.75) 45(3.5,-7.75) 46(4,-7.75) 47(4.5,-7.75) 48(5,-7.75) 49(5.5,-7.75) 50(6,-7.75) 76(6,7.75) 77(5.5,7.75) 78(5,7.75) 79(4.5,7.75) 80(4,7.75) 81(3.5,7.75) 82(3,7.75) 83(2.5,7.75) 84(2,7.75) 85(1.5,7.75) 86(1,7.75) 87(0.5,7.75) 88(0,7.75) 89(-0.5,7.75) 90(-1,7.75) 91(-1.5,7.75) 92(-2,7.75) 93(-2.5,7.75) 94(-3,7.75) 95(-3.5,7.75) 96(-4,7.75) 97(-4.5,7.75) 98(-5,7.75) 99(-5.5,7.75) 100(-6,7.75)
POT3_3352T
  rect 1.651x1.651 hole 1.016: 1(0,0)
  round 1.651 hole 1.016: 2(2.54,0) 3(5.08,0)
QFN8_1P6X1P6MM
  rect 0.457x0.33 smd: 1(-0.6,0.525)
  rect 0.457x0.279 smd: 2(-0.6,0) 3(-0.6,-0.5) 5(0.6,-0.5) 6(0.6,0) 7(0.6,0.5)
  rect 0.279x0.457 smd: 4(0,-0.6) 8(0,0.6)
QFN32_S142EP
  custom 0.07x0.07 smd: 1(-2.4,1.751) 2(-2.4,1.251) 3(-2.4,0.751) 4(-2.4,0.25) 5(-2.4,-0.25) 6(-2.4,-0.751) 7(-2.4,-1.251) 8(-2.4,-1.751) 9(-1.751,-2.4) 10(-1.251,-2.4) 11(-0.751,-2.4) 12(-0.25,-2.4) 13(0.25,-2.4) 14(0.751,-2.4) 15(1.251,-2.4) 16(1.751,-2.4) 17(2.4,-1.751) 18(2.4,-1.251) 19(2.4,-0.751) 20(2.4,-0.25) 21(2.4,0.25) 22(2.4,0.751) 23(2.4,1.251) 24(2.4,1.751) 25(1.751,2.4) 26(1.251,2.4) 27(0.751,2.4) 28(0.25,2.4) 29(-0.25,2.4) 30(-0.751,2.4) 31(-1.251,2.4) 32(-1.751,2.4)
  rect 3.607x3.607 smd: 33(0,0)
RC0402_25
  round 0.635 smd: 1(-0.508,0) 2(0.508,0)
RC0603_OV
  oval 0.889x1.143 smd: 1(-0.762,0) 2(0.762,0)
RC0805_OV
  oval 0.889x1.524 smd: 1(-0.965,0) 2(0.965,0)
RC1206_OV
  oval 1.016x1.778 smd: 1(-1.524,0) 2(1.524,0)
SH0603
  rect 0.991x0.813 smd: 1(-0.8,0) 2(0.8,0)
SH_HDR102_BOTTOM
  rect 1.524x1.524 hole 1.016: 1(0,0)
  round 1.524 hole 1.016: 2(0,-2.54)
SO8_1P27_4X5
  rect 1.6x0.61 smd: 1(-2.7,1.905) 2(-2.7,0.635) 3(-2.7,-0.635) 4(-2.7,-1.905) 5(2.7,-1.905) 6(2.7,-0.635) 7(2.7,0.635) 8(2.7,1.905)
SOD123W
  rect 1.219x1.219 smd: A(1.4,0) C(-1.4,0)
SOD323
  rect 0.889x1.219 smd: A(0,1.27) C(0,-1.27)
SOD-128
  rect 1.397x2.108 smd: A(-2.2,0) C(2.2,0)
SON20_0P5_3P6X5P6
  rect 0.305x0.94 smd: 1(-2.25,-1.65) 2(-1.75,-1.65) 3(-1.25,-1.65) 4(-0.75,-1.65) 5(-0.25,-1.65) 6(0.25,-1.65) 7(0.75,-1.65) 8(1.25,-1.65) 9(1.75,-1.65) 10(2.25,-1.65) 11(2.25,1.65) 12(1.75,1.65) 13(1.25,1.65) 14(0.75,1.65) 15(0.25,1.65) 16(-0.25,1.65) 17(-0.75,1.65) 18(-1.25,1.65) 19(-1.75,1.65) 20(-2.25,1.65)
  rect 4.851x1.854 smd: 21(0,0)
SOT23-6_A
  rect 1.219x0.61 smd: 1(-1.25,0.95) 2(-1.25,0) 3(-1.25,-0.95) 4(1.25,-0.95) 5(1.25,0) 6(1.25,0.95)
SOT23_5S
  rect 0.686x0.991 smd: 1(-0.953,-1.295) 2(0,-1.295) 3(0.953,-1.295) 4(0.953,1.295) 5(-0.953,1.295)
SOT891_6P_0P35_1P05X1P05
  rect 0.635x0.152 smd: 1(-0.412,0.35) 2(-0.412,0) 3(-0.412,-0.35) 4(0.412,-0.35) 5(0.412,0) 6(0.412,0.35)
SW4_SPST_4P8X3P6_2P5
  rect 1.499x0.991 smd: 1(2.575,0.85) 2(2.575,-0.85) 3(-2.575,0.85) 4(-2.575,-0.85)
TEST_LOOP
  round 1.524 hole 1.016: 1(0,0)
TPAD_030
  round 0.762 smd: 1(0,0)
UDFN6_1X1P5MM
  rect 0.584x0.305 smd: 1(-0.418,0.5)
  rect 0.508x0.305 smd: 2(-0.38,0) 3(-0.38,-0.5) 4(0.38,-0.5) 5(0.38,0) 6(0.38,0.5)
unnamed#2
  round 0.254 hole 3.175 unplated: (0,0)
XQFN8_1P45X1P25MM
  rect 0.787x0.203 smd: 1(-0.75,0)
  rect 0.203x0.711 smd: 2(-0.4,-0.65) 3(0,-0.65) 4(0.4,-0.65) 6(0.4,0.65) 7(0,0.65) 8(-0.4,0.65)
  rect 0.711x0.203 smd: 5(0.75,0)
XTAL2_3P3X2P6
  rect 1.6x2.718 smd: 1(-1,0) 2(1,0)
XTAL3_3P35X1P45_SM
  rect 0.406x2.108 smd: 1(1.2,0) 2(0,0) 3(-1.2,0)

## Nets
GND: C1.2 C2.2 C3.2 C4.2 C5.2 C6.2 C7.2 C8.2 C9.2 C10.2 C11.2 C12.2 C16.2 C17.2 C18.2 C19.2 C20.2 C21.2 C22.2 C23.2 C24.2 C25.2 C26.2 C27.2 C28.2 C29.2 C40.2 C43.2 C47.2 C49.2 C59.2 C126.2 C127.2 C128.2 C129.2 C131.2 C133.2 C137.2 C140.2 C141.2 C142.2 C143.2 C144.2 C145.2 C146.2 C147.2 C148.2 C533.2 C535.2 C536.2 C537.2 C538.2 D3.C(CATHODE) D7.A(ANODE) D17.1(C1) D18.1(C1) D19.1(C1) J2.13 J3.11 J3.13 J5.12 J6.12 J7.5(GND) J11.4 J12.3(A2) J12.5(A3) J13.4 J14.3(A2) J14.5(A3) J16.2 J16.3 J16.SH1(SHIELD1) J16.SH2(SHIELD2) L2.2 R13.3(B) R16.2 R20.2 R31.2 R44.2 R51.2 R62.2 R68.2 R74.2 R170.1 SW5.1 SW5.3 SW9.2 SW9.4 TP1.1(PIN1) TP17.1(PIN1) TP32.1(PIN1) U1.4(GND) U2.3(DIR) U2.4(GND) U4.2(GND) U7.2(GND) U8.2(VSS1) U8.8(VSSA) U8.33(EPAD) U9.2(GND) U10.2(GND) U11.2(GND) U15.2(GND) U17.13(VREFL) U17.14(VSS1) U17.37(VSS2) U17.60(VSS3) U17.86(VSS4) U19.1(GND1) U19.4(GND2) U19.16(GND3) U19.19(GND4) U19.21(EP) U21.5(GND) U26.4(GND) U28.4(GND) U29.2(GND) U30.4(GND) U31.2(GND) U31.5(DIR) U32.4(GND) U33.2(GND) Y1.2
P3V3: C24.1 J3.7 J10.1 R63.1 TP13.1(PIN1) U15.5(VOUT)
P3V3_SDA: C3.1 C6.1 C7.1 C10.1 C12.1 C18.1 C19.1 C26.1 J9.1 J12.1(A1) R1.2 R3.1 R12.1 R15.1 R30.1 R39.2 R42.1 R52.1 R60.1 R77.1 U1.1(VCCA) U2.7(VCCA) U4.1(VCCA) U7.1(VCCA) U8.1(VDD1) U8.7(VDDA) U8.11(VBAT) U9.5(VCC) U10.1(VCCA)
P5V0: C21.1 C22.1 J3.9 J10.3 J107.2 R64.1 R169.1 TP14.1(PIN1) U15.1(VIN)
P5V0_SDA_USB_CONN_VBUS: D17.2(C2) J7.1(VBUS) L1.1
P5V_SBC: C27.1 C538.1 J107.1 R530.1 R535.1 R536.1 R538.1 R556.2 R558.2 R559.1 R560.2 R562.2 R564.1 TP15.1(PIN1) U19.5(V1) U26.1(VCCA) U28.1(VCCA) U29.1(VCCA) U30.1(VCCA) U31.1(VCCA) U32.1(VCCA) U33.1(VCCA)
P5V_SDA: C11.1 C15.1 C25.1 L1.2 R14.1 R57.1 R70.1 U8.6(VREGIN) U11.1(VIN)
P5V_SDA_PSW: J107.3 U11.6(VOUT)
VBATT: D9.A(ANODE) J11.2 J16.1 TP38.1(PIN1)
VDD: C49.1 C537.1 D11.A1(ANODE1) D11.A2(ANODE2) D11.A3(ANODE3) J3.3 J5.10 J6.10 J10.2 J14.1(A1) J15.1 R13.1(A) R56.2 R63.2 R64.2 R117.1 R121.1 SH1.2 SW2.2 SW2.4 SW3.2 SW3.4 TP4.1(PIN1) TP9.1(PIN1) TP16.1(PIN1) U26.8(VCCB) U28.8(VCCB) U29.6(VCCB) U30.8(VCCB) U31.6(VCCB) U32.8(VCCB) U33.6(VCCB)
VDD_MCU: C43.1 C129.1 C131.1 C133.1 C137.1 C140.1 C141.1 C142.1 C143.1 C144.1 C145.1 C146.1 C147.1 J15.2 R99.1 R103.1 R117.2 U17.10(VDD1) U17.11(VDDA) U17.38(VDD2) U17.61(VDD3) U17.87(VDD4)
VIN: D13.A(ANODE) J3.1 J3.15
ADC0_SE12: C5.1 R13.2(WIPER) R164.2 TP5.1(PIN1)
AREF: J2.15 R109.2
BTN0: C16.1 R44.1 R152.2 SW2.1 SW2.3
BTN1: C28.1 R74.1 R153.2 SW3.1 SW3.3
CAN_HI: J13.1 J109.1 TP19.1(PIN1) U19.18(CANH)
CAN_LO: J13.2 J108.1 TP22.1(PIN1) U19.17(CANL)
JTAG_TCLK/SWD_CLK: J8.2 J14.4(B2) R127.2 TP31.1(PIN1)
JTAG_TDI: R120.2 R128.2
JTAG_TDO: R119.2 R123.2
JTAG_TMS/SWD_DIO_PTA4: J14.2(B1) J106.2 R121.2 R122.2 TP34.1(PIN1)
LEDRGB_BLUE: D11.C3(CATHODE3) R95.1 TP28.1(PIN1)
LEDRGB_GREEN: D11.C2(CATHODE2) R96.1 TP29.1(PIN1)
LEDRGB_RED: D11.C1(CATHODE1) R97.1 TP30.1(PIN1)
LIN: C17.1 J11.1 R80.1 R171.1 TP18.1(PIN1) U21.6(LIN)
LIN_RX: R130.1 U28.7(B1)
LIN_RX_LS: R538.2 TP35.1(PIN1) U21.1(RXD) U28.2(A1)
LIN_SLP: R529.1 R530.2 U21.2(S\L\P\)
LIN_TX: R131.1 U28.6(B2)
LIN_TX_LS: TP37.1(PIN1) U21.4(TXD) U28.3(A2)
LVLRST_EN: R1.1 U1.5(OE)
MIC2005_CSLEW: C15.2 U11.5(CSLEW)
POWER_EN: R69.1 U8.31(ADC0_SE7B/PTD6/SPI0_PCS3/UART0_)
PTA0: J5.7 U17.79(PTA0/ADC0_SE0/CMP0_IN0/FTM2_CH1)
PTA1: J5.5 U17.78(PTA1/ADC0_SE1/CMP0_IN1/FTM1_CH1)
PTA2: R540.2 R542.1 SH11.1 U17.73(PTA2/ADC1_SE0/FTM3_CH0/LPI2C0_S)
PTA3: R539.2 R541.1 SH12.1 U17.72(PTA3/ADC1_SE1/FTM3_CH1/LPI2C0_S)
PTA4: R122.1 R546.2 U17.98(PTA4/JTAG_TMS/SWD_DIO/CMP0_OUT/)
PTA6: R147.2 U17.58(PTA6/ADC0_SE2/FTM0_FLT1/LPSPI1_)
PTA7: J5.9 U17.57(PTA7/ADC0_SE3/FTM0_FLT2/RTC_CLK)
PTA8: J6.17 U17.100(PTA8/LPUART2_RX/LPSPI2_SOUT/FXI)
PTA9: J6.19 U17.99(PTA9/LPUART2_TX/LPSPI2_PCS0/FXI)
PTA10: R123.1 R545.2 U17.92(PTA10/JTAG_TDO/NOETM_TRACE_SWO/)
PTA11: J1.2 U17.91(PTA11/FTM1_CH5/FXIO_D1/CMP0_RRT)
PTA12: J6.16 U17.90(PTA12/FTM1_CH6/CAN1_RX/FTM2_QD_)
PTA13: J6.14 U17.89(PTA13/FTM1_CH7/CAN1_TX/FTM2_QD_)
PTA14: J2.16 U17.88(PTA14/FTM0_FLT0/FTM3_FLT1/EWM_I)
PTA15: R167.1 U17.83(PTA15/ADC1_SE12/FTM1_CH2/LPSPI0)
PTA16: R165.1 U17.82(PTA16/ADC1_SE13/FTM1_CH3/LPSPI1)
PTA17: J1.4 U17.62(PTA17/FTM0_CH6/FTM3_FLT0/E\W\M\)
PTB0: J4.5 U17.54(PTB0/ADC0_SE4/ADC1_SE14/LPUART0)
PTB1: J4.7 U17.53(PTB1/ADC0_SE5/ADC1_SE15/LPUART0)
PTB2: J2.11 U17.48(PTB2/ADC0_SE6/FTM1_CH0/LPSPI0_S)
PTB3: J2.9 U17.47(PTB3/ADC0_SE7/FTM1_CH1/LPSPI0_S)
PTB4: J2.7 U17.28(PTB4/FTM0_CH4/LPSPI0_SOUT/TRGMU)
PTB5: J2.5 U17.27(PTB5/FTM0_CH5/LPSPI0_PCS1/LPSPI)
PTB6: R81.2 R84.1 U17.16(PTB6/XTAL/LPI2C0_SDA)
PTB6_XTAL: C127.1 R84.2 R91.2 Y3.2
PTB7: R88.1 R90.2 U17.15(PTB7/EXTAL/LPI2C0_SCL)
PTB7_EXTAL: C126.1 R88.2 R91.1 Y3.1
PTB8: J1.5 U17.77(PTB8/FTM3_CH0)
PTB9: J1.7 U17.76(PTB9/FTM3_CH1/LPI2C0_SCLS)
PTB10: J1.9 U17.75(PTB10/FTM3_CH2/LPI2C0_SDAS)
PTB11: J1.11 U17.74(PTB11/FTM3_CH3/LPI2C0_HREQ)
PTB12: J4.3 U17.68(PTB12/ADC1_SE7/FTM0_CH0/FTM3_FL)
PTB13: J5.11 U17.67(PTB13/ADC1_SE8/ADC0_SE8/FTM0_CH)
PTB14: J4.8 R124.1 U17.66(PTB14/ADC1_SE9/ADC0_SE9/FTM0_CH)
PTB15: J4.10 R125.1 U17.65(PTB15/ADC1_SE14/FTM0_CH3/LPSPI1)
PTB16: J4.12 R126.1 U17.64(PTB16/ADC1_SE15/FTM0_CH4/LPSPI1)
PTB17: J4.6 R129.2 U17.63(PTB17/FTM0_CH5/LPSPI1_PCS3)
PTC0: R146.2 R534.1 U17.40(PTC0/ADC0_SE8/FTM0_CH0/LPSPI2_S)
PTC1: J5.13 R172.2 R525.2 U17.39(PTC1/ADC0_SE9/FTM0_CH1/LPSPI2_S)
PTC2: J5.15 R527.2 R528.2 U17.30(PTC2/ADC0_SE10/CMP0_IN5/FTM0_CH)
PTC3: J4.16 R132.2 R533.1 U17.29(PTC3/ADC0_SE11/CMP0_IN4/FTM0_CH)
PTC4: J3.12 R127.1 U17.96(PTC4/JTAG_TCLK/SWD_CLK/CMP0_IN2)
PTC5: J3.10 R128.1 U17.95(PTC5/JTAG_TDI/FTM2_CH0/RTC_CLKO)
PTC6: J4.4 R161.1 U17.81(PTC6/ADC1_SE4/LPUART1_RX/CAN1_R)
PTC7: J4.2 R162.1 U17.80(PTC7/ADC1_SE5/LPUART1_TX/CAN1_T)
PTC8: J6.9 U17.56(PTC8/LPUART1_RX/FTM1_FLT0/LPUAR)
PTC9: J6.11 U17.55(PTC9/LPUART1_TX/FTM1_FLT1/LPUAR)
PTC10: R133.2 U17.52(PTC10/FTM3_CH4/TRGMUX_IN11)
PTC11: R134.2 U17.51(PTC11/FTM3_CH5/TRGMUX_IN10)
PTC12: J2.10 R152.1 U17.50(PTC12/FTM3_CH6/FTM2_CH6/LPUART2)
PTC13: J2.12 R153.1 U17.49(PTC13/FTM3_CH7/FTM2_CH7/LPUART2)
PTC14: J4.14 R164.1 U17.46(PTC14/ADC0_SE12/FTM1_CH2/LPSPI2)
PTC15: J5.20 U17.45(PTC15/ADC0_SE13/FTM1_CH3/LPSPI2)
PTC16: J6.8 U17.44(PTC16/ADC0_SE14/FTM1_FLT2/CAN2_)
PTC17: J6.6 U17.43(PTC17/ADC0_SE15/FTM1_FLT3/CAN2_)
PTD0: J2.6 J6.1 R156.1 U17.4(PTD0/FTM0_CH2/LPSPI1_SCK/FTM2_C)
PTD1: J6.2 U17.3(PTD1/FTM0_CH3/LPSPI1_SIN/FTM2_C)
PTD2: SH13.2 U17.71(PTD2/ADC1_SE2/FTM3_CH4/LPSPI1_S)
PTD3: J1.14 J6.4 U17.70(PTD3/ADC1_SE3/FTM3_CH5/LPSPI1_P)
PTD4: J4.1 U17.69(PTD4/ADC1_SE6/FTM0_FLT3/FTM3_FL)
PTD5: J1.12 U17.33(PTD5/FTM2_CH3/LPTMR0_ALT2/FTM2_)
PTD6: J5.18 R130.2 U17.32(PTD6/CMP0_IN7/LPUART2_RX/FTM2_F)
PTD7: J5.16 R131.2 U17.31(PTD7/CMP0_IN6/LPUART2_TX/FTM2_F)
PTD8: J6.7 U17.42(PTD8/FTM2_FLT2/FTM1_CH4)
PTD9: J6.5 U17.41(PTD9/FTM2_FLT3/FTM1_CH5)
PTD10: J1.6 R166.1 U17.36(PTD10/FTM2_CH0/FTM2_QD_PHB)
PTD11: J1.8 R168.1 U17.35(PTD11/FTM2_CH1/FTM2_QD_PHA/LPUA)
PTD12: J1.10 U17.34(PTD12/FTM2_CH2/LPUART2_RTS)
PTD13: J2.1 U17.25(PTD13/FTM2_CH4/LPUART1_RX/RTC_C)
PTD14: J2.3 U17.24(PTD14/FTM2_CH5/LPUART1_TX/CLKOU)
PTD15: J2.2 R154.1 U17.22(PTD15/FTM0_CH0/LPSPI0_SCK)
PTD16: J2.4 R155.1 U17.21(PTD16/FTM0_CH1/LPSPI0_SIN/CMP0_)
PTD17: J6.13 U17.20(PTD17/FTM0_FLT2/LPUART2_RX)
PTE0: J3.6 U17.94(PTE0/LPSPI0_SCK/TCLK1/LPSPI1_SO)
PTE1: J5.14 U17.93(PTE1/LPSPI0_SIN/LPI2C0_HREQ/LPS)
PTE2: J4.13 U17.85(PTE2/ADC1_SE10/LPSPI0_SOUT/LPTM)
PTE3: J1.16 U17.18(PTE3/FTM0_FLT0/LPUART2_RTS/FTM2)
PTE4: J6.20 R137.2 U17.9(PTE4/FTM2_QD_PHB/FTM2_CH2/CAN0_)
PTE5: J6.18 R136.2 U17.8(PTE5/TCLK2/FTM2_QD_PHA/FTM2_CH3)
PTE6: J4.15 U17.84(PTE6/ADC1_SE11/LPSPI0_PCS2/FTM3)
PTE7: J2.14 U17.59(PTE7/FTM0_CH7/FTM3_FLT0)
PTE8: J2.8 R135.2 U17.26(PTE8/CMP0_IN3/FTM0_CH6)
PTE9: J3.8 R529.2 U17.23(PTE9/FTM0_CH7/LPUART2_CTS)
PTE10: R543.1 R567.2 U17.6(PTE10/CLKOUT/LPSPI2_PCS1/FTM2_C)
PTE11: R544.1 R568.2 U17.5(PTE11/LPSPI2_PCS0/LPTMR0_ALT1/F)
PTE12: J6.15 U17.19(PTE12/FTM0_FLT3/LPUART2_TX)
PTE13: J5.8 R532.2 U17.7(PTE13/LPSPI2_PCS2/FTM2_FLT0)
PTE14: J5.6 U17.17(PTE14/FTM0_FLT1/FTM2_FLT1)
PTE15: J5.4 U17.2(PTE15/LPUART1_CTS/LPSPI2_SCK/FT)
PTE16: J5.2 U17.1(PTE16/LPUART1_RTS/LPSPI2_SIN/FT)
PWR_LED: D3.A(ANODE) R56.1
RGB_BLUE: R95.2 R156.2
RGB_GREEN: R96.2 R155.2
RGB_RED: R97.2 R154.2
RST_TGTMCU_B: D1.C(CATHODE) J3.5 J14.10(B5) J104.3 R4.2 R5.2 R563.2 U1.7(B1) U17.97(PTA5/R\E\S\E\T\/TCLK1)
SBC_CAN_RX: R137.1 U30.6(B2)
SBC_CAN_RX_LS: TP20.1(PIN1) U19.7(RXD) U30.3(A2)
SBC_CAN_TX: R136.1 U30.7(B1)
SBC_CAN_TX_LS: TP21.1(PIN1) U19.2(TXD) U30.2(A1)
SBC_CS: R129.1 U31.4(B)
SBC_CS_LS: TP33.1(PIN1) U19.20(S\C\S\) U31.3(A)
SBC_LIMP: R532.1 U33.4(B)
SBC_LIMP_LS: R536.2 R566.1 TP502.1(PIN1) U19.11(L\I\M\P\)
SBC_MISO: R125.2 U29.4(B)
SBC_MISO_LS: TP23.1(PIN1) U19.9(SDO) U29.3(A)
SBC_MOSI: R126.2 U26.6(B2)
SBC_MOSI_LS: TP25.1(PIN1) U19.3(SDI) U26.3(A2)
SBC_RST: R565.1 TP24.1(PIN1) U19.8(R\S\T\)
SBC_SCK: R124.2 U26.7(B1)
SBC_SCK_LS: TP27.1(PIN1) U19.10(SCK) U26.2(A1)
SDA_EXTAL: C23.1 U8.17(EXTAL0/PTA18/FTM0_FLT2/FTM_CLKI) Y1.3
SDA_JTAG_TCLK: J12.4(B2) U8.12(JTAG_TCLK/SWD_CLK/EZP_CLK/TSI0_)
SDA_JTAG_TDI: J12.8(B4) U8.13(JTAG_TDI/EZP_DI/TSI0_CH2/PTA1/U)
SDA_JTAG_TDO: J12.6(B3) U8.14(JTAG_TDO/TRACE_SWO/EZP_DO/TSI0_)
SDA_JTAG_TMS: J12.2(B1) R77.2 U8.15(JTAG_TMS/SWD_DIO/TSI0_CH4/PTA3/)
SDA_LED: D2.C(CATHODE) U8.29(PTD4/SPI0_PCS1/U\A\R\T\0\_\R\T\)
SDA_LED_R: D2.A(ANODE) R12.2
SDA_RST: J12.10(B5) R57.2 R62.1 TP12.1(PIN1) U8.19(R\E\S\E\T\)
SDA_RST_LED: D1.A(ANODE) R2.1
SDA_RST_TGTMCU_B: J105.2 U8.21(ADC0_SE9/TSI0_CH6/PTB1/I2C0_SDA)
SDA_RST_TGTMCU_J_B: J104.1 J105.1 R3.2 R5.1 U1.2(A1)
SDA_RX_EN: R15.2 R16.1 U4.5(DIR)
SDA_SPI0_CS: R38.2 TP7.1(PIN1) U8.23(ADC0_SE4B/CMP1_IN0/TSI0_CH15/PT)
SDA_SPI0_RST_B: R41.2 TP8.1(PIN1) U8.22(ADC0_SE15/TSI0_CH14/PTC1/SPI0_P)
SDA_SPI0_SCK: U8.26(PTC5/SPI0_SCK/LPTMR0_ALT2/I2S0_) U10.3(A)
SDA_SPI0_SIN: U2.5(2A) U8.28(CMP0_IN1/PTC7/SPI0_SIN/USB_SOF_)
SDA_SPI0_SOUT: U7.3(A) U8.27(CMP0_IN0/PTC6/SPI0_SOUT/PDB0_EX)
SDA_SWD_EN: R41.1 R47.1 U9.6(Y1)
SDA_SWD_EN_B: R49.2 U8.16(N\M\I\/E\Z\P\_\C\S\/TSI0_CH5/PT)
SDA_SWD_EN_B_R: R42.2 R49.1 U9.1(A1)
SDA_SWD_EN_R: R47.2 R51.1 R52.2 U10.5(DIR)
SDA_SWD_OE: R35.1 R38.1 U9.4(Y2)
SDA_SWD_OE_B: R32.2 U8.20(ADC0_SE8/TSI0_CH0/PTB0/I2C0_SCL)
SDA_SWD_OE_B_R: R32.1 R39.1 U9.3(A2)
SDA_SWD_OE_R: R30.2 R31.1 R35.2 U7.5(DIR)
SDA_USB_CONN_DN: D19.2(C2) J7.2(D-) R25.1
SDA_USB_CONN_DP: D18.2(C2) J7.3(D+) R21.1
SDA_USB_DN: R25.2 U8.4(USB0_DM)
SDA_USB_DP: R21.2 U8.3(USB0_DP)
SDA_USB_P5V_SENSE: R14.2 R20.1 U8.30(ADC0_SE6B/PTD5/SPI0_PCS2/U\A\R\)
SDA_USBSHIELD: J7.6(SHELL1) J7.7(SHELL2) J7.8(SHELL3) J7.9(SHELL4) J7.10(SHELL5) L2.1
SDA_VOUT33: C9.1 J9.2 U8.5(VOUT33)
SDA_XTAL: C20.1 U8.18(XTAL0/PTA19/FTM1_FLT0/FTM_CLKIN) Y1.1
SW1_RST_B: C1.1 J104.2 SW5.2 SW5.4
SWD_CLK_TGTMCU_BUF: J8.1 U10.4(B)
SWD_DIO_TGTMCU_BUF: J106.1 U2.2(2B) U7.4(B)
TC_EXTAL_TP: TP11.1(PIN1) U8.10(EXTAL32)
TC_SDA_USB_ID_TP: J7.4(ID) TP6.1(PIN1)
TC_XTAL_TP: TP10.1(PIN1) U8.9(XTAL32)
TP_2102_A: TP500.1(PIN1) U1.3(A2)
TP_2102_B: TP501.1(PIN1) U1.6(B2)
UART1_RX_TGTMCU_BUF: R24.1 U4.4(B)
UART1_RX_TGTMCU_R: U4.3(A) U8.25(PTC4/SPI0_PCS0/UART1_TX/FTM0_CH)
UART1_TX_TGTMCU_BUF: R18.1 U2.1(1B)
UART1_TX_TGTMCU_R: U2.6(1A) U8.24(CMP1_IN1/PTC3/SPI0_PCS1/UART1_R)
UART_RX: R24.2 R161.2
UART_TX: R18.2 R162.2
V_TGTMCU: C2.1 C4.1 C8.1 R2.2 R4.1 SH1.1 U1.8(VCCB) U2.8(VCCB) U4.6(VCCB) U7.6(VCCB) U10.6(VCCB)
VREFH: C148.1 D7.C(CATHODE) R99.2 R103.2 R109.1 U17.12(VREFH)
VSUP: C29.1 C47.1 C128.1 D6.A D9.C(CATHODE) D13.C(CATHODE) Q1.1(EMITTER1) Q1.2(EMITTER2) Q1.3(EMITTER3) R537.1 TP36.1(PIN1) U19.14(BAT) U21.7(VBAT)
VTRG_EN: R68.1 R69.2 R70.2 U11.3(ENABLE)
VTRG_FAULT_B: R60.2 U8.32(PTD7/CMT_IRO/UART0_TX/FTM0_CH7/) U11.4(F\A\U\L\T\)
N20335552: J14.6(B3) R119.1
N20335572: J14.8(B4) R120.1
N20337946: J5.3 R165.2 R166.2
N20338949: J5.1 R167.2 R168.2
N20340793: J6.3 SH13.1
N20341657: J1.13 R132.1 R133.1
N20341806: J1.15 R134.1 R135.1
N20342040: J2.19 R539.1 R567.1
N20342083: J2.17 R540.1 R568.1
N20344687: J4.11 R146.1 R541.2 R543.2
N20344693: J4.9 R147.1 R542.2 R544.2
N20408163: R169.2 R170.2 U15.3(EN)
N20408770: C59.1 U15.4(BYP)
N20447644: J1.1 SH11.2
N20447648: J1.3 SH12.2
N20483325: J3.2 R81.1
N20483330: J3.4 R90.1
N20483362: J3.14 R545.1
N20483368: J3.16 R546.1
N20487643: C533.1 R525.1 R533.2
N20487701: R527.1 SW8.1
N20487722: C535.1 R528.1 R534.2
N20498073: Q1.4(BASE) U19.15(VEXCTRL)
N20501046: R537.2 SW9.1 SW9.3 U19.12(WAKE)
N20514938: Q1.5(COLLECTOR) R535.2 U19.6(VEXCC)
N20519466: C536.1 U19.13(V2)
N20529258: D6.C R80.2 R171.2
N20533540: R172.1 SW7.1
N20579312: C40.1 R92.1 R98.1
N20579404: J109.2 R92.2
N20579447: J108.2 R98.2
N20615890: R556.1 U26.5(OE)
N20616554: R558.1 U28.5(OE)
N20618570: R559.2 U29.5(DIR)
N20622415: R560.1 U30.5(OE)
N20627960: R562.1 U32.5(OE)
N20628442: R563.1 U32.7(B1)
N20629363: R564.2 U33.5(DIR)
N20629726: R565.2 U32.2(A1)
N20631005: R566.2 U33.3(A)

Pads without a net: J2 18 20; J5 17 19; J11 3; J12 7 9; J13 3; J14 7 9; U21 3 8; U32 3 6

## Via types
v1: diameter 0.508, hole 0.254, TOP to BOTTOM, 518 vias
v2: diameter 1.016, hole 0.711, TOP to BOTTOM, 3 vias
v3: diameter 0.61, hole 0.356, TOP to BOTTOM, 28 vias
v4: diameter 0.457, hole 0.203, TOP to BOTTOM, 359 vias

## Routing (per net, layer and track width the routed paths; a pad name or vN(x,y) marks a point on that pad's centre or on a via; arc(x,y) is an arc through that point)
GND: length 738.5
  TOP w0.152: 8.34,42.53 8.34,42.53 D19.1 8.67,42.94 ; 8.41,41.8 8.42,41.8 D17.1 8.86,41.45 ; 8.76,44.46 D18.1 8.32,44.79
  TOP w0.178: U9.2 v1(36.02,39.65)
  TOP w0.203: U1.4 7.34,52.59 v1(7.11,52.82) ; U26.4 38.95,23.77 ; 42.4,23.79 U30.4 ; 46.06,18.4 U32.4 ; U28.4 v1(46.31,23.77)
  TOP w0.254: 46.06,18.4 46.11,18.35 46.16,18.35 v1(46.52,17.99) ; U8.2 v1(18.1,42.9) ; 51.19,20.93 U31.5 U31.2 v1(49.06,20.93) ; C141.2 74.61,19.51 74.87,19.77 U17.37 ; U2.3 29.65,48.31 v1(29.84,48.5) ; v1(15.6,17.78) 15.64,17.74 U19.16 ; C3.2 v1(10.72,50.76) ; U17.60 85.33,27.66 C143.2 ; U17.13 v1(68.93,29.16) ; C538.2 v1(51.38,22.58) ; v1(15.66,16.05) 15.85,16.24 U19.19 ; U29.2 49.2,24.15 49.2,24.14 48.78,24.14 v4(48.58,23.94) ; U19.4 v1(20.92,17.24) ; U8.8 v1(16.16,39.75) ; C133.2 v3(77.3,44.33) ; U10.2 27.95,38.12 v1(27.77,37.88) ; U33.2 49.1,17.82 v4(48.85,18.06) ; C26.2 v1(19.33,30.03) ; v1(1.62,52.75) 1.49,52.62 C2.2 ; U2.4 v1(29.05,48.61) ; v1(68.92,28.37) 68.64,28.66 U17.14 ; U17.86 76.37,38.66 76.63,38.92 C142.2 ; v1(39.2,23.09) 39.2,23.52 38.95,23.77 ; U7.2 v1(27.8,41.16) ; U4.2 v1(27.85,44.44)
  TOP w0.381: 31.61,45.87 R16.2 ; R16.2 32.46,45.87 ; R16.2 32.03,45.96 ; 22.72,34.63 Y1.2 ; Y1.2 24.48,32.87 ; Y1.2 24.31,32.7 ; Y1.2 22.55,34.46 ; Y1.2 23.71,33.86 ; Y1.2 22.38,34.29 ; Y1.2 23.15,33.3 ; Y1.2 24.14,32.53 ; 6.21,38.37 L2.2 ; L2.2 5.62,38.42 ; L2.2 5.62,39.31 ; L2.2 6.21,39.36 ; C128.2 45.43,12.33 ; C128.2 44.8,12.33 ; C128.2 44.8,14.23 ; C128.2 45.43,13.28 ; C128.2 45.43,14.23 ; C23.2 22.07,34.25 ; C23.2 21.64,35.18 ; C23.2 22.15,34.67 ; C23.2 21.22,35.1 ; R44.2 119.9,33.9 ; R44.2 120.32,33.81 ; R44.2 119.47,33.81 ; R44.2 120.4,33.39 ; C29.2 26.52,14.67 ; C29.2 25.88,13.14 ; C29.2 26.52,13.14 ; C29.2 25.88,14.67 ; 11.15,55.29 SW5.1 ; SW5.1 10.2,56.59 ; SW5.1 12.09,55.97 ; SW5.1 10.2,55.35 ; SW5.1 12.09,55.35 ; SW5.1 12.09,56.59 ; SW5.1 11.15,56.66 ; J16.SH1 13.7,4.64 ; J16.SH1 12.79,4.64 ; J16.SH1 11.87,2.58 ; J16.SH1 13.7,2.58 ; C9.2 14.52,43.83 ; C9.2 13.89,42.31 ; C9.2 14.97,43.38 ; C9.2 13.44,42.76 ; 51.97,26.36 D3.C ; D3.C 52.58,26.37 ; D3.C 51.36,27.52 ; D3.C 52.58,27.52 ; D3.C 51.36,26.37 ; D3.C 52.58,26.94 ; D3.C 51.36,26.94 ; C146.2 88.2,26.39 ; C146.2 88.2,27.03 ; C146.2 86.67,27.03 ; C146.2 87.43,26.39 ; C538.2 51.06,22.16 ; C538.2 50.63,23.09 ; C538.2 50.63,22.07 ; C538.2 51.06,23.01 ; C17.2 5.51,37.97 ; C17.2 4.75,37.97 ; C17.2 6.28,37.97 ; C17.2 6.28,37.34 ; 58.1,28.09 C126.2 ; C126.2 58.52,28.18 ; C126.2 58.61,28.6 ; C126.2 57.68,28.18 ; C25.2 10.48,29.82 ; C25.2 9.98,30.33 ; C25.2 10.4,30.25 ; C25.2 10.4,29.4 ; C12.2 15.08,38.99 ; C12.2 13.56,38.99 ; C12.2 14.32,38.36 ; C12.2 13.56,38.36 ; 61.06,34.64 C144.2 ; C144.2 61.48,34.73 ; C144.2 61.91,34.64 ; C144.2 60.97,34.22 ; J16.SH2 23.6,2.58 ; J16.SH2 22.69,4.64 ; J16.SH2 21.77,2.58 ; J16.SH2 23.6,4.64 ; J16.SH2 21.77,4.64 ; TP17.1 95.78,45.76 ; TP17.1 94.09,46.5 ; TP17.1 95.57,46.5 ; TP17.1 95.57,45.02 ; TP17.1 94.09,45.02 ; TP17.1 93.88,45.76 ; TP17.1 94.83,44.81 ; TP17.1 94.83,46.71 ; 10.91,29.63 R68.2 ; R68.2 11.84,30.05 ; R68.2 10.82,30.05 ; R68.2 11.75,29.63 ; J7.5 v1(5.41,45.32) ; 74.19,19.36 C141.2 ; C141.2 74.19,18.52 ; C141.2 74.1,18.94 ; C27.2 28.95,34.66 ; C27.2 29.9,34.02 ; C27.2 28,34.66 ; C27.2 29.9,34.66 ; C127.2 58.1,27.71 ; C127.2 57.68,27.63 ; C127.2 58.52,27.63 ; C127.2 58.61,27.2 ; 19,29.54 C26.2 ; C26.2 19.42,29.63 ; C26.2 18.91,29.12 ; 108.64,55.12 TP1.1 ; TP1.1 108.64,56.59 ; TP1.1 110.12,55.12 ; TP1.1 110.12,56.59 ; TP1.1 110.33,55.85 ; TP1.1 109.38,56.81 ; TP1.1 109.38,54.9 ; TP1.1 108.43,55.85 ; SW5.3 6.94,55.35 ; SW5.3 5.99,55.29 ; SW5.3 5.05,55.97 ; SW5.3 5.05,56.59 ; SW5.3 6.94,56.59 ; SW5.3 5.99,56.66 ; SW5.3 5.05,55.35 ; 42.36,5.9 J3.13 ; J3.13 43.92,4.34 ; J3.13 43.14,6.13 ; J3.13 42.13,5.12 ; J3.13 42.36,4.34 ; J3.13 44.16,5.12 ; U21.5 22.56,27.2 ; U21.5 21.56,27.08 ; U21.5 21.56,26.33 ; U21.5 22.56,26.21 ; U21.5 23.55,26.33 ; U21.5 23.55,26.7 ; U21.5 23.55,27.08 ; C28.2 119.9,28.68 ; C28.2 119.47,28.59 ; C28.2 120.4,28.17 ; C28.2 120.32,28.59 ; C137.2 76,14.88 ; C137.2 76,15.52 ; C137.2 74.48,15.52 ; C137.2 74.48,14.88 ; C133.2 78.07,43.96 ; C133.2 76.54,43.33 ; C133.2 78.07,43.33 ; C133.2 76.54,43.96 ; 25.6,52.6 J2.13 ; J2.13 25.6,54.16 ; J2.13 26.38,54.39 ; J2.13 25.36,53.38 ; J2.13 27.16,52.6 ; J2.13 26.38,52.36 ; C22.2 32.5,34.23 ; C22.2 33.27,34.23 ; C22.2 33.27,33.6 ; C22.2 31.74,34.23 ; 6.36,9.89 SW9.2 ; SW9.2 8.24,9.89 ; SW9.2 7.3,8.58 ; SW9.2 8.24,9.27 ; SW9.2 7.3,9.96 ; SW9.2 8.24,8.65 ; SW9.2 6.36,8.65 ; C5.2 116.26,47.77 ; C5.2 115.75,47.26 ; C5.2 115.84,47.68 ; C5.2 116.68,47.68 ; C19.2 32.45,35.6 ; C19.2 32.45,36.45 ; C19.2 32.54,36.03 ; J13.4 2.82,16.63 ; J13.4 2.04,14.83 ; J13.4 2.04,16.4 ; J13.4 3.84,15.62 ; J13.4 1.81,15.62 ; J13.4 2.82,14.6 ; J13.4 3.6,16.4 ; J13.4 3.6,14.83 ; C47.2 35.68,20.58 ; C47.2 34.15,19.94 ; C47.2 34.15,20.58 ; C47.2 35.68,19.94 ; C47.2 34.92,20.58 ; 5.42,15.79 C40.2 ; C40.2 5.42,16.42 ; C40.2 6.95,15.79 ; C40.2 6.18,16.42 ; C40.2 6.95,16.42 ; 96.04,28 C533.2 ; C533.2 96.04,29.53 ; C533.2 96.67,28 ; 119.82,43.7 R13.3 ; R13.3 120.06,42.92 ; R13.3 120.84,42.69 ; R13.3 121.85,43.7 ; R13.3 121.62,44.49 ; R13.3 120.84,44.72 ; R13.3 120.06,44.49 ; R13.3 121.62,42.92 ; J3.11 41.62,5.12 ; J3.11 40.6,6.13 ; J3.11 41.38,5.9 ; J3.11 41.38,4.34 ; J3.11 39.59,5.12 ; J3.11 39.82,5.9 ; J3.11 39.82,4.34 ; 85.54,1.8 J5.12 ; J5.12 87.34,2.58 ; J5.12 87.1,1.8 ; J5.12 86.32,3.59 ; J5.12 86.32,1.56 ; J5.12 85.31,2.58 ; J5.12 87.1,3.36 ; J5.12 85.54,3.36 ; 12.77,7.96 J16.2 ; J16.2 13.69,11.8 ; J16.2 14.6,11.8 ; J16.2 13.69,7.96 ; J16.2 14.6,7.96 ; J16.2 12.77,9.88 ; J16.2 14.6,9.88 ; J16.2 12.77,11.8 ; J16.3 19.8,9.88 ; J16.3 17.97,7.96 ; J16.3 19.8,7.96 ; J16.3 18.89,11.8 ; J16.3 18.89,7.96 ; J16.3 19.8,11.8 ; J16.3 17.97,9.88 ; J16.3 17.97,11.8 ; 2.15,8.58 SW9.4 ; SW9.4 2.15,9.96 ; SW9.4 1.21,9.27 ; SW9.4 1.21,9.89 ; SW9.4 1.21,8.65 ; SW9.4 3.09,9.89 ; SW9.4 3.09,8.65 ; R62.2 26.84,36.55 ; R62.2 27.26,36.47 ; R62.2 27.35,36.04 ; C4.2 4.94,50.05 ; C4.2 4.52,49.12 ; C4.2 4.94,49.2 ; 8.85,40.28 C11.2 ; C11.2 8.93,40.7 ; C11.2 9.35,40.79 ; C11.2 9.78,40.7 ; C16.2 120.4,30.28 ; C16.2 119.89,29.77 ; C16.2 119.47,29.85 ; C16.2 120.32,29.85 ; 51.54,20 C537.2 ; C537.2 52.38,20 ; C537.2 51.96,19.92 ; C537.2 52.47,20.42 ; C537.2 51.45,20.42 ; TP32.1 38.63,47.66 ; TP32.1 38.42,48.4 ; TP32.1 37.68,48.62 ; TP32.1 36.94,48.4 ; TP32.1 36.73,47.66 ; 2.04,28.98 J11.4 ; J11.4 3.6,28.98 ; J11.4 3.6,27.41 ; J11.4 2.82,29.21 ; J11.4 1.81,28.19 ; J11.4 2.04,27.41 ; J11.4 3.84,28.19 ; J11.4 2.82,27.18 ; 57.35,36.13 C131.2 ; C131.2 56.71,37.66 ; C131.2 56.71,36.89 ; C131.2 56.71,36.13 ; 21.81,35.37 C20.2 ; C20.2 22.32,34.86 ; C20.2 22.74,34.95 ; C20.2 21.9,35.79 ; C145.2 64.09,34.64 ; C145.2 63.67,34.73 ; C145.2 63.24,34.64 ; C145.2 64.18,34.22 ; J6.12 79.48,55.14 ; J6.12 78.7,54.9 ; J6.12 77.92,55.14 ; J6.12 79.72,55.92 ; J6.12 77.92,56.7 ; J6.12 79.48,56.7 ; J6.12 77.69,55.92 ; 85.11,27.37 C143.2 ; C143.2 86.12,27.37 ; C143.2 86.04,26.95 ; C143.2 85.62,26.87 ; C143.2 85.19,26.95 ; D7.A 53.13,34.07 ; D7.A 53.93,32.85 ; D7.A 52.33,32.85 ; D7.A 53.93,33.44 ; D7.A 52.33,33.44 ; D7.A 53.93,34.02 ; D7.A 52.33,34.02 ; 56.71,40.3 C147.2 ; C147.2 56.71,41.06 ; C147.2 56.71,41.83 ; 28.33,42.27 C8.2 ; C8.2 28.33,43.28 ; C8.2 27.9,43.2 ; 53.74,32.22 C148.2 ; C148.2 54.37,30.69 ; C148.2 54.37,32.22 ; C148.2 53.74,30.69 ; U19.1 20.55,15.74 ; U19.1 20.55,15.53 ; U19.1 19.88,15.4 ; 96.01,16.9 C535.2 ; C535.2 96.01,15.38 ; C535.2 96.65,16.9 ; C21.2 31.6,34.25 ; C21.2 30.07,33.61 ; C21.2 31.6,33.61 ; C21.2 30.07,34.25 ; 56.71,38.57 C43.2 ; C43.2 56.71,39.33 ; C43.2 56.71,37.81 ; 27.98,35.6 C18.2 ; C18.2 27.98,36.45 ; C18.2 28.41,36.54 ; C18.2 27.9,36.03 ; C536.2 11.7,22.71 ; C536.2 11.06,21.76 ; C536.2 11.7,20.8 ; C536.2 11.06,22.71 ; C536.2 11.06,20.8 ; C140.2 63,34.64 ; C140.2 62.58,34.73 ; C140.2 62.15,34.64 ; R74.2 120.32,24.56 ; R74.2 119.47,24.56 ; R74.2 120.4,24.99 ; R74.2 119.9,24.48
  TOP w0.508: SW9.2 v1(5.97,9.27) ; C18.2 v1(28.41,35.09) ; C7.2 20.08,44.67 v1(20.11,44.7) ; L2.2 v1(5.04,38.87) ; U11.2 v1(9.03,34.12) ; C4.2 v1(5.28,49.63) ; C10.2 v1(38.63,40.69) ; R16.2 v1(32.9,45.45) ; R68.2 v1(11.33,29.08) ; R20.2 v1(21.15,44.93) ; R51.2 32.75,37.11 v1(32.9,36.96) ; v3(37.52,33.66) U15.2 36.34,33.72 R170.1 ; C535.2 v1(95.77,16.14) ; C17.2 v1(4.37,37.34) ; C16.2 v1(118.94,30.28) ; C1.2 v1(11.71,53.25) ; SW5.3 v1(7.33,55.97) ; C24.2 v1(43.27,27.76) ; SW5.1 v1(9.86,55.97) ; C8.2 v1(27.58,42.77) ; SW9.4 v1(3.6,9.27) ; C9.2 v1(13.79,43.48) ; C59.2 v1(41.39,33.72) ; C6.2 v1(19.27,45.56) ; C19.2 v1(32.03,35.06) ; C11.2 v1(10.16,40.28) ; R62.2 27.45,35.43 v1(27.45,35.05) ; C5.2 v1(118.06,47.26) ; C533.2 v1(95.65,28.76) ; v3(77.04,40.62) 76.63,40.22 C142.2 ; C25.2 v1(9.98,28.92) ; U21.5 v1(21.1,26.7) ; v4(33.04,7.98) C49.2 ; R31.2 v1(32.94,42.18)
  TOP w0.635: v1(51.97,28.32) D3.C ; R44.2 v1(118.89,33.39) ; R74.2 v1(118.94,24.99) ; C22.2 30.85,33.6 C21.2 v3(30.84,34.65) ; C49.2 31.97,7.61 v1(32.52,7.05) ; v3(51.7,31.53) 53.13,32.97 D7.A ; C137.2 v1(75.24,14.38) ; v3(57.35,42.86) C147.2 v3(57.35,39.88) C43.2 C131.2 C129.2 ; C28.2 v1(119.09,28.17) ; C27.2 v3(27.53,34.02) ; C148.2 v3(53.39,31.46) ; C29.2 v3(25.49,13.9)
  L2_GND w0.381: 12.77,7.96 J16.2 ; J16.2 13.69,11.8 ; J16.2 13.69,7.96 ; J16.2 14.6,9.88 ; J16.2 14.6,7.96 ; J16.2 12.77,11.8 ; J16.2 14.6,11.8 ; J16.2 12.77,9.88 ; J2.13 27.39,53.38 ; J2.13 25.6,52.6 ; J2.13 25.6,54.16 ; J2.13 27.16,54.16 ; J2.13 27.16,52.6 ; J2.13 25.36,53.38 ; J2.13 26.38,54.39 ; J2.13 26.38,52.36 ; J16.3 19.8,11.8 ; J16.3 19.8,9.88 ; J16.3 17.97,9.88 ; J16.3 18.89,11.8 ; J16.3 17.97,7.96 ; J16.3 19.8,7.96 ; J16.3 17.97,11.8 ; J16.3 18.89,7.96 ; J3.11 40.6,6.13 ; J3.11 39.59,5.12 ; J3.11 39.82,4.34 ; J3.11 41.62,5.12 ; J3.11 39.82,5.9 ; J3.11 41.38,4.34 ; J3.11 41.38,5.9 ; J3.11 40.6,4.1 ; R13.3 121.62,44.49 ; R13.3 119.82,43.7 ; R13.3 120.84,44.72 ; R13.3 120.84,42.69 ; R13.3 120.06,44.49 ; R13.3 121.85,43.7 ; R13.3 121.62,42.92 ; R13.3 120.06,42.92 ; 36.73,47.66 TP32.1 ; TP32.1 37.68,48.62 ; TP32.1 37.68,46.71 ; TP32.1 36.94,48.4 ; TP32.1 36.94,46.93 ; TP32.1 38.42,46.93 ; TP32.1 38.63,47.66 ; TP32.1 38.42,48.4 ; J13.4 3.84,15.62 ; J13.4 2.04,16.4 ; J13.4 1.81,15.62 ; J13.4 2.04,14.83 ; J13.4 2.82,14.6 ; J13.4 3.6,16.4 ; J13.4 3.6,14.83 ; J13.4 2.82,16.63 ; 86.32,1.56 J5.12 ; J5.12 85.31,2.58 ; J5.12 86.32,3.59 ; J5.12 85.54,3.36 ; J5.12 87.1,3.36 ; J5.12 87.1,1.8 ; J5.12 87.34,2.58 ; J5.12 85.54,1.8 ; 21.77,4.64 J16.SH2 ; J16.SH2 22.69,4.64 ; J16.SH2 21.77,2.58 ; J16.SH2 23.6,2.58 ; J16.SH2 23.6,4.64 ; 108.43,55.85 TP1.1 ; TP1.1 110.12,55.12 ; TP1.1 108.64,55.12 ; TP1.1 109.38,56.81 ; TP1.1 108.64,56.59 ; TP1.1 110.33,55.85 ; TP1.1 110.12,56.59 ; TP1.1 109.38,54.9 ; TP17.1 94.83,46.71 ; TP17.1 95.78,45.76 ; TP17.1 95.57,45.02 ; TP17.1 95.57,46.5 ; TP17.1 93.88,45.76 ; TP17.1 94.09,46.5 ; TP17.1 94.09,45.02 ; TP17.1 94.83,44.81 ; J11.4 3.6,28.98 ; J11.4 1.81,28.19 ; J11.4 2.82,27.18 ; J11.4 3.84,28.19 ; J11.4 2.82,29.21 ; J11.4 2.04,27.41 ; J11.4 3.6,27.41 ; J11.4 2.04,28.98 ; 77.92,56.7 J6.12 ; J6.12 78.7,56.93 ; J6.12 79.72,55.92 ; J6.12 77.92,55.14 ; J6.12 79.48,56.7 ; J6.12 79.48,55.14 ; J6.12 77.69,55.92 ; J6.12 78.7,54.9 ; 42.36,5.9 J3.13 ; J3.13 43.92,5.9 ; J3.13 43.92,4.34 ; J3.13 43.14,6.13 ; J3.13 44.16,5.12 ; J3.13 42.36,4.34 ; J3.13 42.13,5.12 ; J3.13 43.14,4.1 ; J16.SH1 12.79,4.64 ; J16.SH1 13.7,2.58 ; J16.SH1 11.87,2.58 ; J16.SH1 13.7,4.64
  L3_MIX w0.381: R13.3 121.62,42.92 ; R13.3 119.82,43.7 ; R13.3 120.84,42.69 ; R13.3 120.84,44.72 ; R13.3 120.06,42.92 ; R13.3 121.85,43.7 ; R13.3 121.62,44.49 ; R13.3 120.06,44.49 ; J16.SH1 13.7,2.58 ; J16.SH1 11.87,2.58 ; J16.SH1 13.7,4.64 ; J16.SH1 12.79,4.64 ; J3.13 43.92,5.9 ; J3.13 44.16,5.12 ; J3.13 43.92,4.34 ; 25.36,53.38 J2.13 ; J2.13 25.6,52.6 ; J2.13 26.38,54.39 ; J2.13 25.6,54.16 ; J2.13 27.39,53.38 ; J2.13 26.38,52.36 ; J2.13 27.16,52.6 ; J2.13 27.16,54.16 ; 36.73,47.66 TP32.1 ; TP32.1 37.68,48.62 ; TP32.1 37.68,46.71 ; TP32.1 36.94,46.93 ; TP32.1 36.94,48.4 ; TP32.1 38.63,47.66 ; TP32.1 38.42,48.4 ; TP32.1 38.42,46.93 ; TP1.1 110.12,56.59 ; TP1.1 108.64,56.59 ; TP1.1 110.33,55.85 ; TP1.1 108.64,55.12 ; TP1.1 109.38,56.81 ; TP1.1 110.12,55.12 ; TP1.1 108.43,55.85 ; TP1.1 109.38,54.9 ; 77.69,55.92 J6.12 ; J6.12 77.92,55.14 ; J6.12 79.48,56.7 ; J6.12 79.72,55.92 ; J6.12 77.92,56.7 ; J6.12 78.7,54.9 ; J6.12 79.48,55.14 ; J13.4 3.6,16.4 ; J13.4 3.6,14.83 ; J13.4 1.81,15.62 ; J13.4 2.04,14.83 ; J13.4 2.04,16.4 ; J13.4 3.84,15.62 ; J13.4 2.82,14.6 ; J13.4 2.82,16.63 ; 94.83,44.81 TP17.1 ; TP17.1 94.09,46.5 ; TP17.1 95.57,46.5 ; TP17.1 93.88,45.76 ; TP17.1 95.78,45.76 ; TP17.1 94.83,46.71 ; TP17.1 95.57,45.02 ; TP17.1 94.09,45.02 ; 17.97,7.96 J16.3 ; J16.3 19.8,11.8 ; J16.3 17.97,9.88 ; J16.3 18.89,7.96 ; J16.3 17.97,11.8 ; J16.3 19.8,9.88 ; J16.3 19.8,7.96 ; J16.3 18.89,11.8 ; J11.4 3.84,28.19 ; J11.4 2.82,27.18 ; J11.4 1.81,28.19 ; J11.4 3.6,28.98 ; J11.4 2.04,27.41 ; J11.4 2.82,29.21 ; J11.4 3.6,27.41 ; J11.4 2.04,28.98 ; J5.12 87.1,3.36 ; J5.12 86.32,3.59 ; J5.12 85.54,1.8 ; J5.12 87.1,1.8 ; J5.12 85.54,3.36 ; J5.12 87.34,2.58 ; J5.12 85.31,2.58 ; J5.12 86.32,1.56 ; 13.69,7.96 J16.2 ; J16.2 13.69,11.8 ; J16.2 12.77,7.96 ; J16.2 14.6,9.88 ; J16.2 14.6,11.8 ; J16.2 14.6,7.96 ; J16.2 12.77,11.8 ; J16.2 12.77,9.88 ; 21.77,4.64 J16.SH2 ; J16.SH2 23.6,4.64 ; J16.SH2 22.69,4.64 ; J16.SH2 21.77,2.58 ; J16.SH2 23.6,2.58
  BOTTOM w0.381: 21.77,4.64 J16.SH2 ; J16.SH2 23.6,4.64 ; J16.SH2 22.69,4.64 ; J16.SH2 23.6,2.58 ; J16.SH2 21.77,2.58 ; TP17.1 95.78,45.76 ; TP17.1 94.09,46.5 ; TP17.1 94.83,44.81 ; TP17.1 95.57,45.02 ; TP17.1 93.88,45.76 ; TP17.1 94.83,46.71 ; TP17.1 95.57,46.5 ; TP17.1 94.09,45.02 ; 78.7,54.9 J6.12 ; J6.12 77.92,56.7 ; J6.12 77.92,55.14 ; J6.12 77.69,55.92 ; J6.12 79.48,56.7 ; J6.12 79.48,55.14 ; J6.12 78.7,56.93 ; 36.94,46.93 TP32.1 ; TP32.1 36.94,48.4 ; TP32.1 38.63,47.66 ; TP32.1 37.68,46.71 ; TP32.1 36.73,47.66 ; TP32.1 37.68,48.62 ; TP32.1 38.42,46.93 ; TP32.1 38.42,48.4 ; J16.SH1 13.7,4.64 ; J16.SH1 11.87,2.58 ; J16.SH1 12.79,4.64 ; J16.SH1 13.7,2.58 ; 1.81,15.62 J13.4 ; J13.4 2.82,16.63 ; J13.4 2.82,14.6 ; J13.4 3.84,15.62 ; J13.4 2.04,16.4 ; J13.4 3.6,14.83 ; J13.4 3.6,16.4 ; J13.4 2.04,14.83 ; J12.3 18.75,29.36 18.76,29.38 ; 42.36,4.34 J3.13 ; J3.13 43.92,4.34 ; J3.13 43.92,5.9 ; J3.13 43.14,4.1 ; J3.13 44.16,5.12 ; J3.13 43.14,6.13 ; J2.13 27.16,52.6 ; J2.13 27.39,53.38 ; J2.13 26.38,54.39 ; J2.13 27.16,54.16 ; J2.13 25.6,54.16 ; J14.3 54.56,40.56 54.57,40.55 ; 14.6,9.88 J16.2 12.77,9.88 ; J12.5 18.75,30.63 18.76,30.65 ; 19.8,9.88 J16.3 17.97,9.88 ; J11.4 3.6,28.98 ; J11.4 2.04,28.98 ; J11.4 3.84,28.19 ; J11.4 2.82,27.18 ; J11.4 3.6,27.41 ; J11.4 2.04,27.41 ; J11.4 1.81,28.19 ; J11.4 2.82,29.21 ; J3.11 41.38,4.34 ; J3.11 40.6,6.13 ; J3.11 41.38,5.9 ; J3.11 39.82,4.34 ; J3.11 40.6,4.1 ; J14.5 54.69,41.83 54.7,41.82
  vias: v1(2.24,12.48) v1(10.1,44.51) v1(10.12,42.85) v1(10.11,41.44) v1(10.42,22.05) v1(11.15,57.04) v1(14.47,30.98) v1(15.45,39.34) v1(18.05,39.02) v1(18.24,20.05) v1(18.23,17.99) v1(18.23,15.84) v1(18.73,39.71) v1(18.83,38.21) v1(19.52,40.53) v1(19.53,38.91) v1(20.2,41.2) v1(20.33,39.71) v1(21.01,40.39) v1(21.39,35.64) v1(22.38,18.02) v1(24.6,32.44) v1(25.02,1.84) v1(29.15,1.35) v1(31.22,10.72) v1(31.72,1.34) v1(32.07,52.03) v1(34.33,1.35) v1(36.75,1.35) v1(39.38,1.35) v1(42.69,23.29) v1(46.44,19.98) v1(47.97,20.23) v1(49.24,4.81) v1(50.65,12.55) v1(51.47,38.21) v1(53.08,28.66) v1(53.8,6.87) v1(54.06,22.26) v1(56.9,43.96) v1(58.21,44.15) v1(58.73,27.94) v1(60.83,40.86) v1(65.38,27.87) v1(70.33,40.94) v1(76.95,31.2) v1(81.29,31.13) v1(86.4,27.04) v1(87.76,46.31) v1(89.4,40.47) v1(94.53,28.73) v1(99.63,1.22) v3(36.05,20.49) v3(45.22,15) v3(46.47,15.03) v3(46.46,13.28) v3(63.97,35.2) v3(64.57,34.22) v3(73.95,18.27) v4(0.78,49.62) v4(0.8,37.85) v4(0.8,35.7) v4(0.8,33.56) v4(0.8,31.41) v4(0.8,29.27) v4(0.8,27.12) v4(0.8,24.98) v4(0.8,22.83) v4(0.8,20.69) v4(0.8,18.54) v4(0.8,16.4) v4(0.8,14.25) v4(0.8,12.11) v4(0.81,9.96) v4(0.86,7.67) v4(1.6,5.45) v4(2.26,13.45) v4(2.67,3.82) v4(3.13,55.03) v4(3.15,48.73) v4(3.42,13.54) v4(3.46,7.32) v4(4.32,48.71) v4(4.37,2.23) v4(4.47,56.17) v4(5.71,47.41) v4(5.71,46.4) v4(5.9,22.89) v4(6.06,24.62) v4(6.23,17) v4(6.41,57.22) v4(6.71,1.11) v4(6.88,49.66) v4(7.11,26.98) v4(8.09,57.55) v4(8.22,27.76) v4(8.8,12.85) v4(8.88,0.8) v4(9.03,11.97) v4(9.23,15.21) v4(9.32,26.16) v4(9.66,24.65) v4(10.23,57.55) v4(10.74,13.2) v4(11.07,0.96) v4(11.14,12.32) v4(11.84,24.72) v4(12.38,57.55) v4(12.38,5.22) v4(12.5,34.57) v4(13.11,33.76) v4(13.45,5.22) v4(13.87,24.68) v4(14.52,57.55) v4(14.52,5.22) v4(14.52,4.15) v4(14.52,3.08) v4(14.52,2) v4(14.52,0.93) v4(15.6,11.66) v4(15.6,10.58) v4(15.57,9.48) v4(15.57,8.38) v4(15.6,5.22) v4(15.6,4.15) v4(15.6,3.08) v4(15.6,2) v4(15.6,0.93) v4(15.71,15.07) v4(16.45,24.78) v4(16.67,57.55) v4(16.67,11.66) v4(16.67,10.58) v4(16.66,9.48) v4(16.66,8.38) v4(16.67,5.22) v4(16.67,4.15) v4(16.67,3.08) v4(16.67,2) v4(16.67,0.93) v4(17.74,11.66) v4(17.74,10.58) v4(17.83,36.14) v4(17.93,24.7) v4(19.25,35.32) v4(19.53,51.65) v4(20.07,57.27) v4(20.14,54.63) v4(20.56,30.9) v4(20.76,50.37) v4(20.96,11.66) v4(20.96,10.58) v4(20.96,5.22) v4(20.97,4.15) v4(20.97,3.08) v4(20.97,2) v4(20.97,0.93) v4(21.44,20.19) v4(21.63,30.9) v4(21.72,51.68) v4(22.03,5.22) v4(22.35,16.19) v4(22.58,54.62) v4(22.55,50.79) v4(22.6,57.32) v4(22.7,30.9) v4(23.11,5.22) v4(24.18,5.22) v4(24.19,4.15) v4(24.19,3.08) v4(24.19,2) v4(24.19,0.93) v4(24.49,46.06) v4(24.76,42.34) v4(25.04,57.3) v4(25.32,6.29) v4(25.43,31.63) v4(25.65,3.23) v4(25.78,43.34) v4(26.09,34.11) v4(26.34,42.3) v4(26.44,32.08) v4(26.59,33.12) v4(27.1,51.95) v4(27.4,32.97) v4(27.65,57.25) v4(27.75,9.07) v4(29.11,7.37) v4(29.72,51.93) v4(30.09,57.23) v4(30.65,48.09) v4(32.68,57.25) v4(33.24,42.99) v4(33.46,46.3) v4(34.33,45.38) v4(35.16,57.21) v4(36.33,37.13) v4(36.89,45.66) v4(37.69,37.83) v4(37.8,57.23) v4(38.42,45.65) v4(40.43,57.06) v4(41.47,6.74) v4(42.26,39.42) v4(42.67,20.26) v4(42.8,57.06) v4(43.27,33.57) v4(43.42,40.02) v4(44.16,25.19) v4(44.47,51.94) v4(44.69,54.51) v4(46.36,51.94) v4(46.61,6.34) v4(46.94,56.85) v4(47.45,3.12) v4(47.67,15.28) v4(49.03,15) v4(49.18,16.83) v4(49.45,54.58) v4(49.55,51.94) v4(49.56,35.61) v4(49.73,6.91) v4(50.14,7.91) v4(50.36,11.47) v4(50.33,10.48) v4(50.32,9.58) v4(50.69,35.62) v4(50.66,34.56) v4(50.74,45.15) v4(51.53,51.96) v4(51.64,29.2) v4(52.02,56.7) v4(53.51,10.49) v4(53.99,51.94) v4(54.58,56.66) v4(54.51,30.3) v4(54.52,15.46) v4(54.74,7.9) v4(54.93,8.89) v4(55.14,25.44) v4(55.28,6.73) v4(55.87,15.38) v4(56.3,52.02) v4(56.5,18.49) v4(56.57,6.76) v4(56.68,14.64) v4(56.74,19.54) v4(56.81,25.43) v4(57.2,56.73) v4(57.29,13.96) v4(57.65,24.56) v4(57.83,18.46) v4(57.93,51.99) v4(58.01,6.7) v4(58.11,13.51) v4(58.6,20.98) v4(58.74,24.84) v4(58.86,19.3) v4(59.25,13.35) v4(59.52,20.21) v4(59.72,56.7) v4(59.75,10.98) v4(60.02,21.76) v4(60.64,44.13) v4(60.69,38.57) v4(60.66,6.68) v4(61.05,23.89) v4(61.01,10.27) v4(61.9,6.49) v4(62.12,23.99) v4(62.21,56.73) v4(62.94,11.43) v4(63.16,6.48) v4(63.36,44.36) v4(64.53,10.39) v4(65.41,15.96) v4(65.52,6.44) v4(65.64,8.95) v4(65.75,12.89) v4(66.67,6.41) v4(66.88,22.3) v4(67.43,17.39) v4(67.73,10.93) v4(68.02,7.37) v4(68.11,22.45) v4(68.69,20.39) v4(69.02,15.63) v4(69.11,6.62) v4(69.3,10.93) v4(69.53,23.1) v4(69.79,52.38) v4(70.42,10.96) v4(70.42,8.14) v4(70.92,5.08) v4(72.73,29.04) v4(72.75,14.2) v4(72.79,13.24) v4(72.78,10.96) v4(72.86,9.31) v4(73.15,50.19) v4(73.16,45.94) v4(73.98,10.96) v4(74.56,35.16) v4(74.95,56.76) v4(75.2,24.9) v4(75.35,12.28) v4(75.35,10.96) v4(75.37,9.31) v4(76.04,22.82) v4(76.66,35.24) v4(76.74,49.8) v4(77.05,12.28) v4(77.03,10.99) v4(77.03,9.28) v4(77.4,54.52) v4(78.05,49.8) v4(78.01,19.56) v4(78,18.48) v4(78.58,47.18) v4(79.35,13.31) v4(79.49,10.96) v4(79.46,9.31) v4(79.55,50.8) v4(79.78,35.22) v4(80.08,19.03) v4(80.25,33.99) v4(80.5,18.33) v4(80.61,48.1) v4(80.71,9.32) v4(80.89,50.23) v4(81.11,26.36) v4(81.38,45.04) v4(81.72,10.96) v4(81.7,9.33) v4(82.3,48.01) v4(82.51,4.41) v4(82.68,46.52) v4(82.9,45.07) v4(82.92,10.99) v4(83.9,48.28) v4(84.18,21.81) v4(84.29,54.65) v4(84.42,52.11) v4(84.43,50.19) v4(84.6,36.27) v4(84.51,35.35) v4(84.64,45.07) v4(84.86,27.06) v4(85.03,4.49) v4(85.16,9.71) v4(85.93,48.91) v4(86,24.46) v4(86.04,22.82) v4(86.01,20.71) v4(86.02,10.76) v4(86.18,48.04) v4(86.41,45.13) v4(86.7,46.58) v4(86.97,38.89) v4(87.66,45.07) v4(87.73,42.59) v4(87.92,9.73) v4(88.2,6.18) v4(88.35,50.84) v4(88.8,12.41) v4(88.95,28.34) v4(89.09,6.67) v4(89.24,52.11) v4(89.79,42.65) v4(89.73,19.94) v4(89.88,48.98) v4(89.98,16.07) v4(90.08,36.24) v4(90.44,28.95) v4(90.61,9.72) v4(90.82,8.12) v4(91.13,22.14) v4(91.16,10.81) v4(91.22,26.38) v4(91.41,31.08) v4(91.41,29.86) v4(91.7,36.51) v4(91.77,33.4) v4(91.87,23.16) v4(92.37,7.05) v4(93.04,9.62) v4(93.51,6.34) v4(93.8,12.2) v4(95.07,27.4) v4(95.21,36.76) v4(95.4,31.17) v4(95.59,24.36) v4(95.62,34.87) v4(96.11,17.19) v4(96.26,20.02) v4(97.99,9.93) v4(98.63,21.64) v4(119,57.25) v4(120.63,56.65) v4(122.11,55.58) v4(123.4,54.26) v4(124.65,51.91) v4(124.94,49.79) v4(124.94,47.65) v4(124.94,45.5) v4(124.94,43.36) v4(124.94,41.21) v4(124.94,39.07) v4(124.94,34.77) v4(124.94,30.48) v4(124.94,28.34) v4(124.94,24.05) v4(124.94,21.9) v4(124.94,17.61) v4(124.94,15.47)
